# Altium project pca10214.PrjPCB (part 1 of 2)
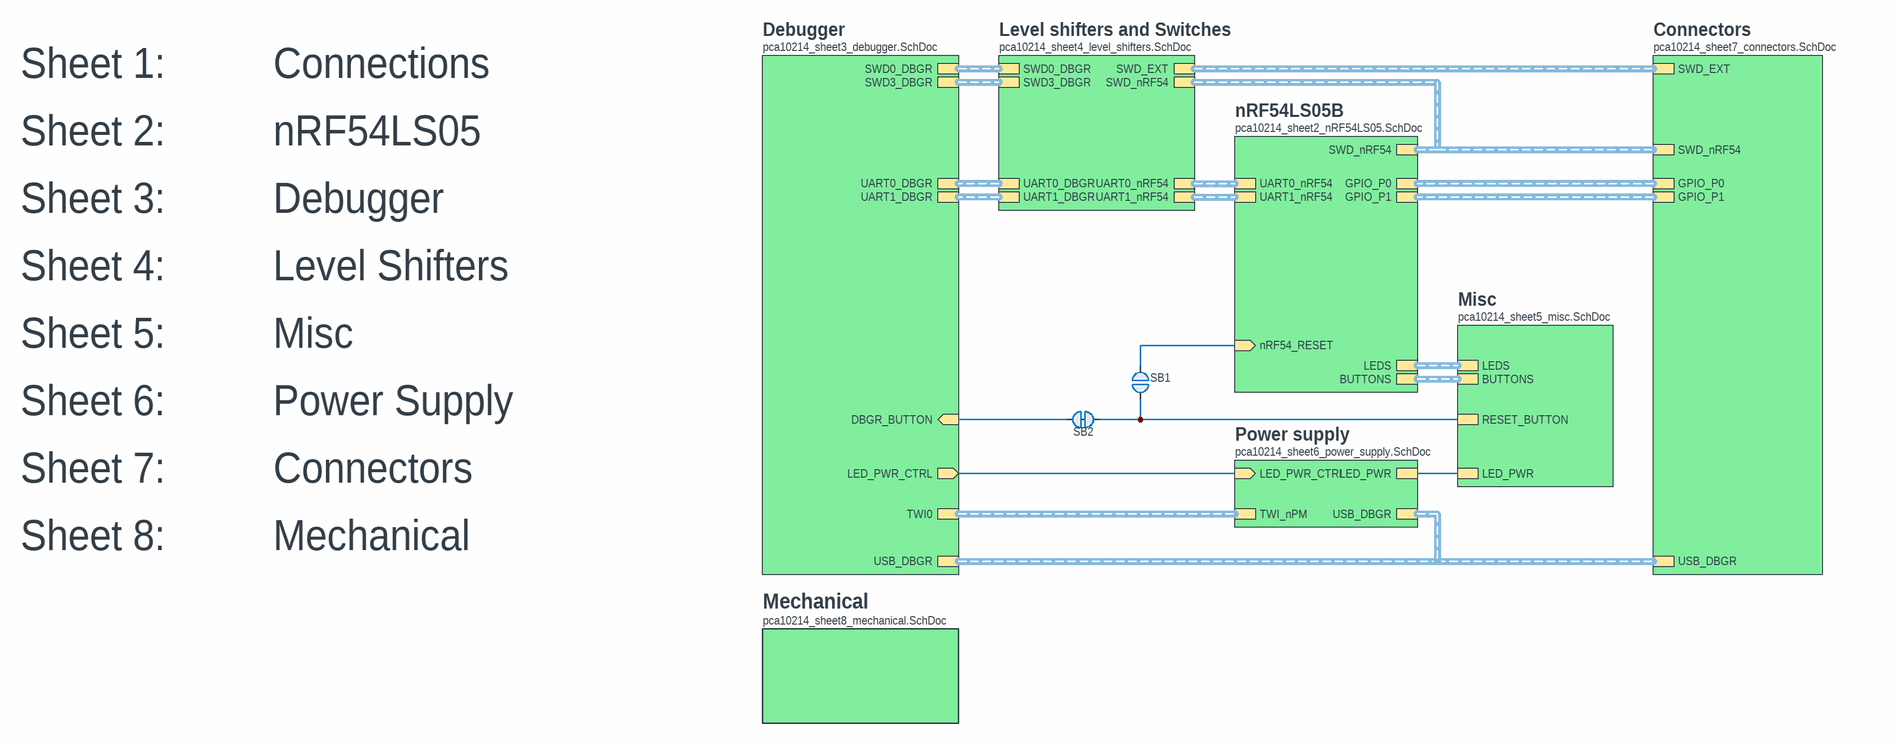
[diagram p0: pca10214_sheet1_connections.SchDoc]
SurfaceFinish: ENIG Gold; SoldermaskColor: Blue; SilkscreenColor: White; ProjectNumber: 4561; ProductName: nRF54LS05-DK; PCBStackup: 4001; PCBRevision: 0116KJP; PCBNumber: 401006; PCARevision: 0.3.1; PCAName: PCA10214; Organization: Nordic Semiconductor; NrOfLayers: 4; Dielectric: FR-4; Designer: KJP; Compliance: RoHS, REACH, Halogen-Free; Classification: PUBLIC; BoardTitle: nRF54LS05 DK; BoardThickness: 1.6mm
8 sheets, 205 parts. Net scope: hierarchical (ports join the sheet entries above them; power ports are global).
Board files: 401006.PcbDoc, 401006 _panel.PcbDoc
Sheets:
  pca10214_sheet1_connections.SchDoc
    nRF54LS05B = pca10214_sheet2_nRF54LS05.SchDoc
    Debugger = pca10214_sheet3_debugger.SchDoc
    Level shifters and Switches = pca10214_sheet4_level_shifters.SchDoc
    Misc = pca10214_sheet5_misc.SchDoc
    Power supply = pca10214_sheet6_power_supply.SchDoc
    Connectors = pca10214_sheet7_connectors.SchDoc
    Mechanical = pca10214_sheet8_mechanical.SchDoc

## Sheet pca10214_sheet1_connections.SchDoc: =BoardTitle+' - Connections'
size A3; Organization: Nordic Semiconductor; DocumentNumber: 1; Revision: 0.3.1; SheetNumber: 1; SheetTotal: 8; Author: KJP; CompanyName: Nordic Semiconductor; DrawnBy: KJP; DocumentSize: A4

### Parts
SB1  Solderbridge  [Solderbridge]  (value not drawn)  (no BOM)
SB2  Solderbridge  [Solderbridge_Shorted]  (value not drawn)  (net tie, no BOM)

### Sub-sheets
Connectors = pca10214_sheet7_connectors.SchDoc: SWD_nRF54 (harness SWD), SWD_EXT (harness SWD), GPIO_P0 (harness GPIO_P0), GPIO_P1 (harness GPIO_P1), USB_DBGR (harness USB)
Debugger = pca10214_sheet3_debugger.SchDoc: DBGR_BUTTON (in), SWD0_DBGR (harness SWD), UART0_DBGR (harness UART_DBGR), USB_DBGR (harness USB), UART1_DBGR (harness UART_DBGR), TWI0 (harness TWI), SWD3_DBGR (harness SWD), LED_PWR_CTRL (out)
Level shifters and Switches = pca10214_sheet4_level_shifters.SchDoc: SWD0_DBGR (harness SWD), SWD_EXT (harness SWD), UART0_nRF54 (harness UART), UART1_nRF54 (harness UART), SWD3_DBGR (harness SWD), SWD_nRF54 (harness SWD), UART0_DBGR (harness UART_DBGR), UART1_DBGR (harness UART_DBGR)
Mechanical = pca10214_sheet8_mechanical.SchDoc: no entries
Misc = pca10214_sheet5_misc.SchDoc: BUTTONS (harness UI), LEDS (harness UI), RESET_BUTTON, LED_PWR
nRF54LS05B = pca10214_sheet2_nRF54LS05.SchDoc: BUTTONS (harness UI), LEDS (harness UI), GPIO_P0 (harness GPIO_P0), UART0_nRF54 (harness UART), GPIO_P1 (harness GPIO_P1), UART1_nRF54 (harness UART), SWD_nRF54 (harness SWD), nRF54_RESET (in)
Power supply = pca10214_sheet6_power_supply.SchDoc: TWI_nPM (harness TWI), LED_PWR_CTRL (in), LED_PWR, USB_DBGR (harness USB)

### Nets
DBGR_BUTTON: SB2.2 ; sheet Debugger/DBGR_BUTTON
LED_PWR_CTRL: sheet Debugger/LED_PWR_CTRL, sheet Power supply/LED_PWR_CTRL
NRESET: SB1.1 ; sheet nRF54LS05B/nRF54_RESET
NetC64_2: sheet Misc/LED_PWR, sheet Power supply/LED_PWR
NetSB1_2: SB1.2 SB2.1 ; sheet Misc/RESET_BUTTON

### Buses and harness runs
harness sheet Connectors/GPIO_P0 = sheet nRF54LS05B/GPIO_P0
harness sheet Connectors/GPIO_P1 = sheet nRF54LS05B/GPIO_P1
harness sheet Connectors/SWD_EXT = sheet Level shifters and Switches/SWD_EXT
harness sheet Connectors/SWD_nRF54 = sheet Level shifters and Switches/SWD_nRF54 = sheet nRF54LS05B/SWD_nRF54
harness sheet Connectors/USB_DBGR = sheet Debugger/USB_DBGR = sheet Power supply/USB_DBGR
harness sheet Debugger/SWD0_DBGR = sheet Level shifters and Switches/SWD0_DBGR
harness sheet Debugger/SWD3_DBGR = sheet Level shifters and Switches/SWD3_DBGR
harness sheet Debugger/TWI0 = sheet Power supply/TWI_nPM
harness sheet Debugger/UART0_DBGR = sheet Level shifters and Switches/UART0_DBGR
harness sheet Debugger/UART1_DBGR = sheet Level shifters and Switches/UART1_DBGR
harness sheet Level shifters and Switches/UART0_nRF54 = sheet nRF54LS05B/UART0_nRF54
harness sheet Level shifters and Switches/UART1_nRF54 = sheet nRF54LS05B/UART1_nRF54
harness sheet Misc/BUTTONS = sheet nRF54LS05B/BUTTONS
harness sheet Misc/LEDS = sheet nRF54LS05B/LEDS

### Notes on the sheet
- Sheet 1:          Connections
- Sheet 2:          nRF54LS05
- Sheet 4:          Level Shifters
- Sheet 3:          Debugger
- Sheet 5:          Misc
- Sheet 6:          Power Supply
- Sheet 7:          Connectors
- Sheet 8:          Mechanical

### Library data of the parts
SB1 = Solderbridge: Manufacturer: N.A.; Part number NEMS: 100500458; Pad Count: 2; Component Status: Active; System: Connector
SB2 = Solderbridge Shorted: Shorted Solderbridge; Manufacturer: N.A.; Part number NEMS: 100500459; Pad Count: 2; Component Status: Active; System: Connector

## Sheet pca10214_sheet2_nRF54LS05.SchDoc: =BoardTitle+' - nRF54LS05B'
size A3; Organization: Nordic Semiconductor; DocumentNumber: 2; Revision: 0.3.1; SheetNumber: 2; SheetTotal: 8; Author: KJP; CompanyName: Nordic Semiconductor; DrawnBy: KJP; DocumentSize: A4
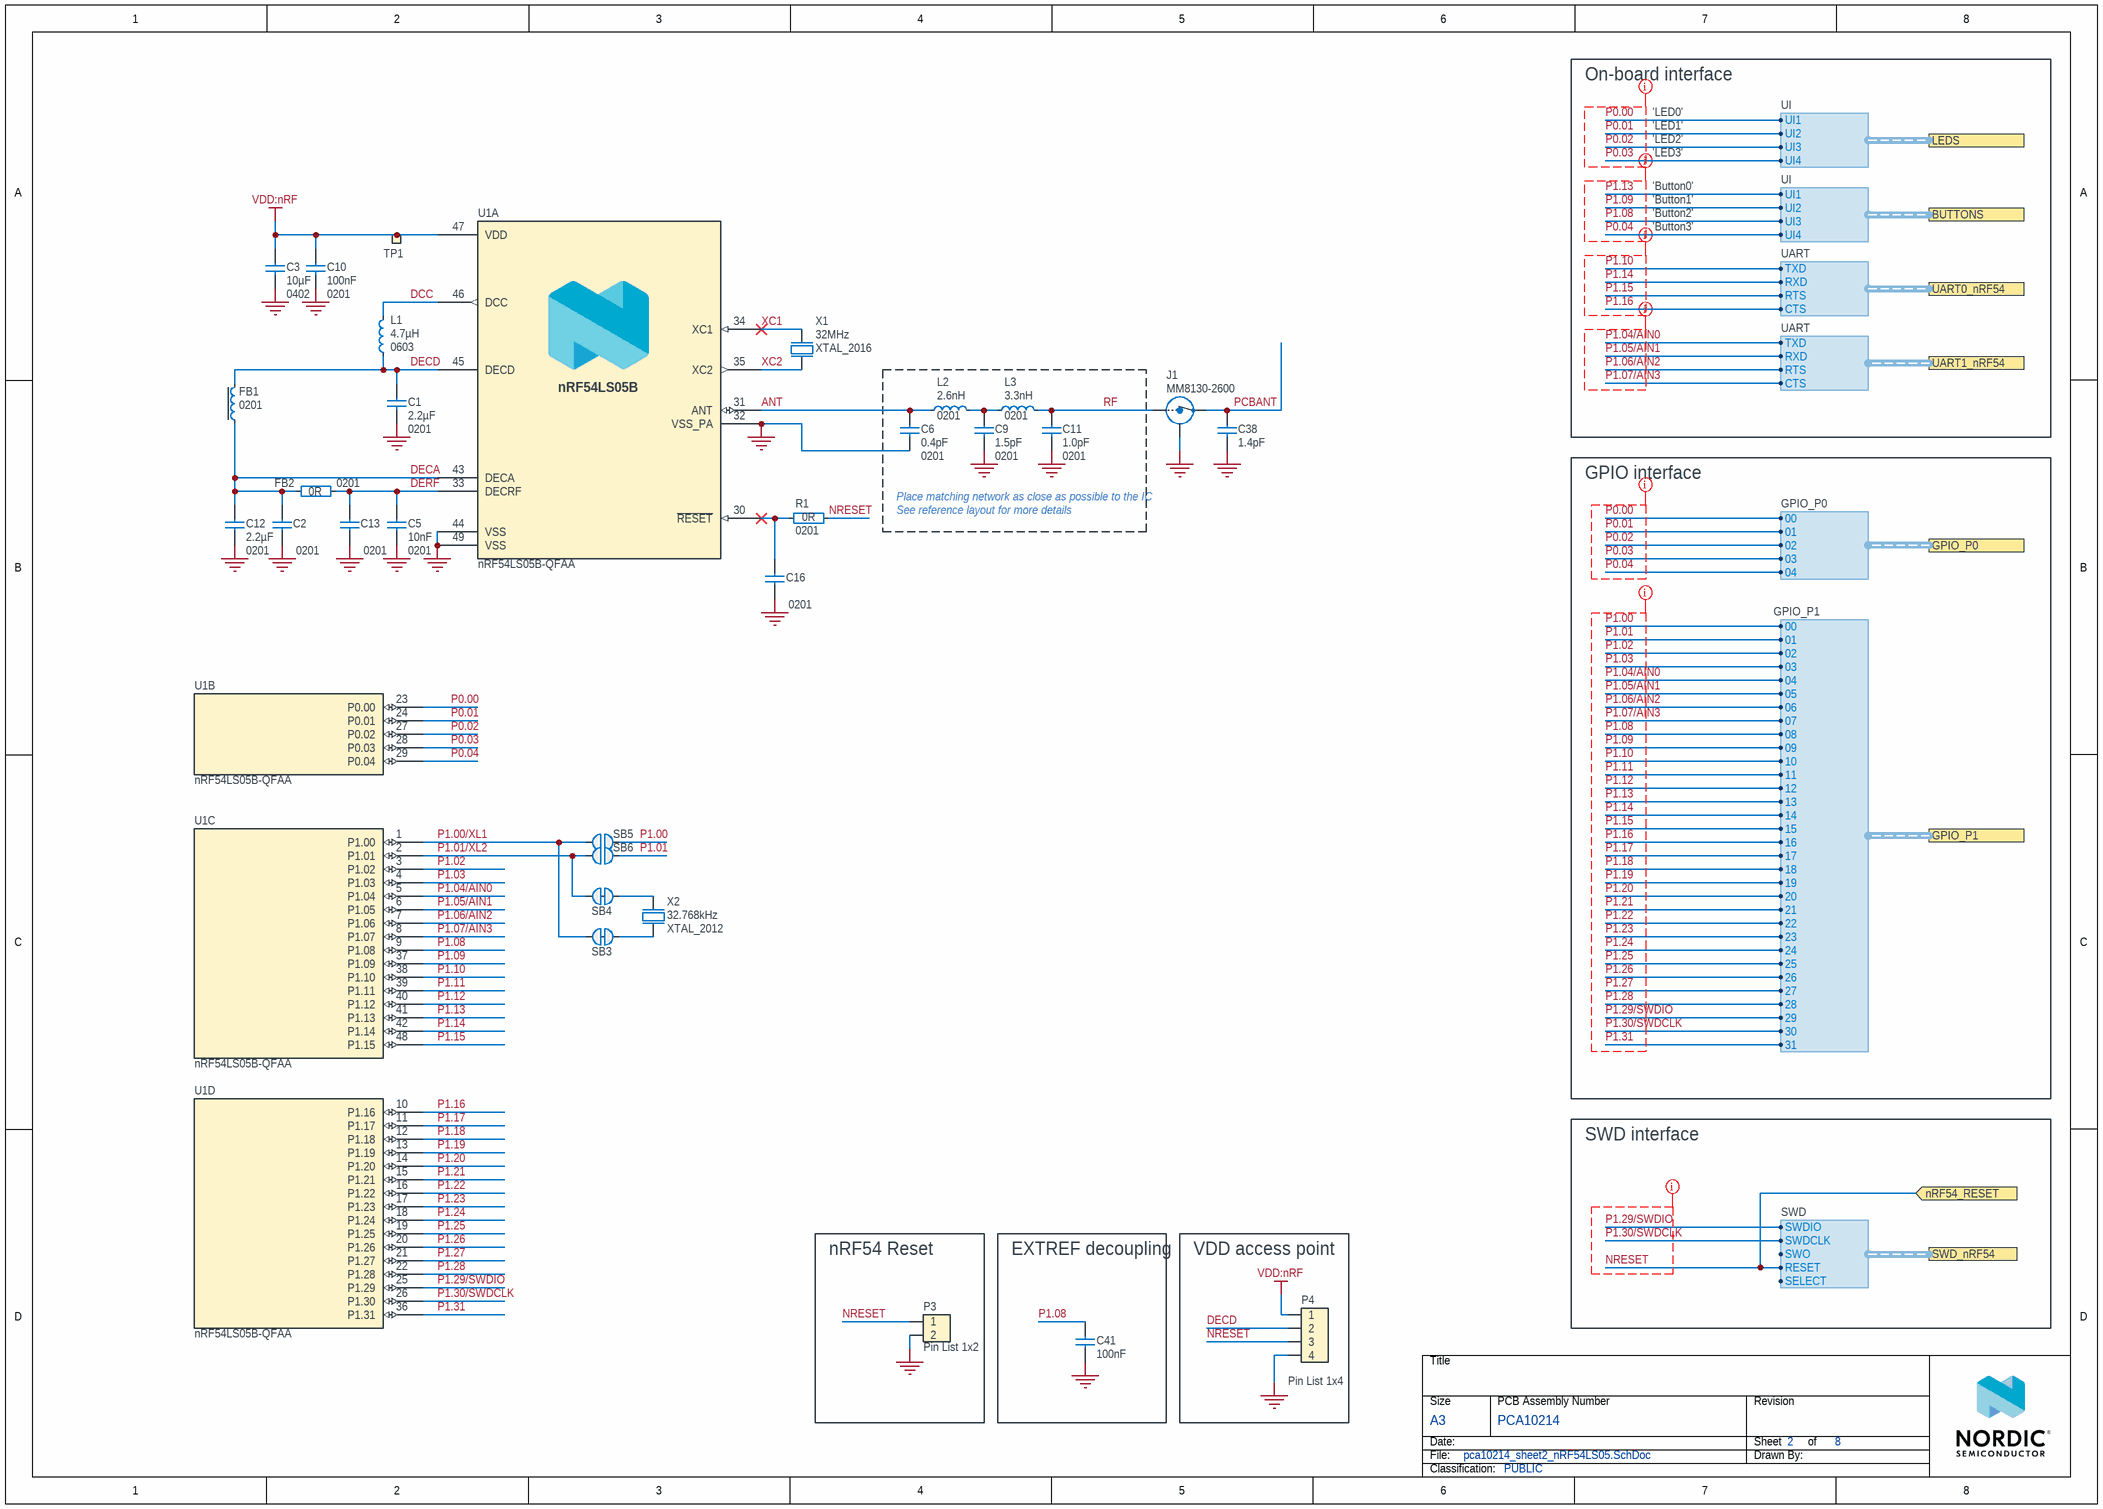
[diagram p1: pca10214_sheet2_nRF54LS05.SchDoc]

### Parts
C1  2.2µF  Footprint Doc: 0201  [CAPC0603X03L_C]
C2  Footprint Doc: 0201  [CAPC0603X03L_C_NC]  (hidden comment: N.C.)
C3  10µF  Footprint Doc: 0402  [CAPC1005X04L]
C5  Footprint Doc: 0201  [CAPC0603X03L_C]  (hidden comment: 10nF)
C6  0.4pF  Footprint Doc: 0201  [CAPC0603X03L_C]
C9  1.5pF  Footprint Doc: 0201  [CAPC0603X03L_C]
C10  100nF  Footprint Doc: 0201  [CAPC0603X03L_C]
C11  1.0pF  Footprint Doc: 0201  [CAPC0603X03L_C]
C12  2.2µF  Footprint Doc: 0201  [CAPC0603X03L_C]
C13  Footprint Doc: 0201  [CAPC0603X03L_C_NC]  (hidden comment: N.C.)
C16  Footprint Doc: 0201  [CAPC0603X03L_C_NC]  (hidden comment: N.C.)
C38  1.4pF  [CAPC0603X03L_C]
C41  100nF  [CAPC1005X04L]
FB1  Footprint Doc: 0201  [INDC0603X03L_C]  (hidden comment: 120R/0.2A)
FB2  Footprint Doc: 0201  [RESC0603X03L_C]  (hidden comment: 0R)
J1  MM8130-2600  [COAXIAL-SWF]
L1  4.7µH  Footprint Doc: 0603  [INDC1608X06L]
L2  2.6nH  Footprint Doc: 0201  [INDC0603X03L_C]
L3  3.3nH  Footprint Doc: 0201  [INDC0603X03L_C]
P3  Pin List 1x2  [LIST_1x2]
P4  Pin List 1x4  [LIST_1x4]
R1  0R  Footprint Doc: 0201  [RESC0603X03L_C]
SB3  Solderbridge  [Solderbridge_SHORTED_0.4]  (value not drawn)  (net tie, no BOM)
SB4  Solderbridge  [Solderbridge_SHORTED_0.4]  (value not drawn)  (net tie, no BOM)
SB5  Solderbridge  [Solderbridge_0.4]  (value not drawn)  (no BOM)
SB6  Solderbridge  [Solderbridge_0.4]  (value not drawn)  (no BOM)
TP1  Ø1.5mm,SMD  [TP_SMD_D1.5mm]  (value not drawn)  (no BOM)
U1  nRF54LS05B-QFAA  [QFN49P40_600x600x90L40x20T460N]  (parts A,B,C,D of 4)
X1  32MHz  Footprint Doc: XTAL_2016  [BT-XTAL_2016]
X2  32.768kHz  [XTAL_2012]

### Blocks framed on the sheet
nRF54 Reset: P3
EXTREF decoupling: C41
VDD access point: P4

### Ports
BUTTONS (harness UI), GPIO_P0 (harness GPIO_P0), GPIO_P1 (harness GPIO_P1), LEDS (harness UI), nRF54_RESET (in), SWD_nRF54 (harness SWD), UART0_nRF54 (harness UART), UART1_nRF54 (harness UART)

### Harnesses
SWD: SWDIO, SWDCLK, SWO, RESET, SELECT
UART: RTS, CTS, RXD, TXD
GPIO_P0: 02, 03, 04, 00, 01
UI: UI2, UI1, UI3, UI4
GPIO_P1: 02, 03, 04, 00, 01, 05, 06, 07, 08, 09, 10, 11, 12, 13, 14, 15, 16, 17, 18, 19, 20, 21, 22, 23, 24, 25, 26, 27, 28, 29, 30, 31

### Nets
GND: C1.1 C2.1 C3.1 C5.1 C6.1 C9.1 C10.2 C11.1 C12.1 C13.1 C16.1 C38.1 C41.1 J1.2(Shield) P3.2 P4.4 U1.32(VSS_PA) U1.44(VSS) U1.49(VSS) X1.2(GND) X1.4(GND)
VDD:nRF: C3.2 C10.1 P4.1 TP1.1 U1.47(VDD)
ANT: C6.2 L2.1 U1.31(ANT)
DCC: L1.1 U1.46(DCC)
DECA: C2.2 C12.2 FB1.2 FB2.2 U1.43(DECA)
DECD: C1.2 FB1.1 L1.2 P4.2 U1.45(DECD)
DERF: C5.2 C13.2 FB2.1 U1.33(DECRF)
NRESET: P3.1 P4.3 R1.2 ; port nRF54_RESET, port SWD_nRF54.RESET
P0.00: U1.23(P0.00) ; port GPIO_P0.00, port LEDS.UI1
P0.01: U1.24(P0.01) ; port GPIO_P0.01, port LEDS.UI2
P0.02: U1.27(P0.02) ; port GPIO_P0.02, port LEDS.UI3
P0.03: U1.28(P0.03) ; port GPIO_P0.03, port LEDS.UI4
P0.04: U1.29(P0.04) ; port GPIO_P0.04, port BUTTONS.UI4
P1.00: SB5.2 ; port GPIO_P1.00
P1.00/XL1: SB3.1 SB5.1 U1.1(P1.00)
P1.01: SB6.2 ; port GPIO_P1.01
P1.01/XL2: SB4.1 SB6.1 U1.2(P1.01)
P1.02: U1.3(P1.02) ; port GPIO_P1.02
P1.03: U1.4(P1.03) ; port GPIO_P1.03
P1.04/AIN0: U1.5(P1.04) ; port UART1_nRF54.TXD, port GPIO_P1.04
P1.05/AIN1: U1.6(P1.05) ; port UART1_nRF54.RXD, port GPIO_P1.05
P1.06/AIN2: U1.7(P1.06) ; port UART1_nRF54.RTS, port GPIO_P1.06
P1.07/AIN3: U1.8(P1.07) ; port UART1_nRF54.CTS, port GPIO_P1.07
P1.08: C41.2 U1.9(P1.08) ; port BUTTONS.UI3, port GPIO_P1.08
P1.09: U1.37(P1.09) ; port BUTTONS.UI2, port GPIO_P1.09
P1.10: U1.38(P1.10) ; port UART0_nRF54.TXD, port GPIO_P1.10
P1.11: U1.39(P1.11) ; port GPIO_P1.11
P1.12: U1.40(P1.12) ; port GPIO_P1.12
P1.13: U1.41(P1.13) ; port BUTTONS.UI1, port GPIO_P1.13
P1.14: U1.42(P1.14) ; port UART0_nRF54.RXD, port GPIO_P1.14
P1.15: U1.48(P1.15) ; port UART0_nRF54.RTS, port GPIO_P1.15
P1.16: U1.10(P1.16) ; port UART0_nRF54.CTS, port GPIO_P1.16
P1.17: U1.11(P1.17) ; port GPIO_P1.17
P1.18: U1.12(P1.18) ; port GPIO_P1.18
P1.19: U1.13(P1.19) ; port GPIO_P1.19
P1.20: U1.14(P1.20) ; port GPIO_P1.20
P1.21: U1.15(P1.21) ; port GPIO_P1.21
P1.22: U1.16(P1.22) ; port GPIO_P1.22
P1.23: U1.17(P1.23) ; port GPIO_P1.23
P1.24: U1.18(P1.24) ; port GPIO_P1.24
P1.25: U1.19(P1.25) ; port GPIO_P1.25
P1.26: U1.20(P1.26) ; port GPIO_P1.26
P1.27: U1.21(P1.27) ; port GPIO_P1.27
P1.28: U1.22(P1.28) ; port GPIO_P1.28
P1.29/SWDIO: U1.25(P1.29) ; port SWD_nRF54.SWDIO, port GPIO_P1.29
P1.30/SWDCLK: U1.26(P1.30) ; port SWD_nRF54.SWDCLK, port GPIO_P1.30
P1.31: U1.36(P1.31) ; port GPIO_P1.31
PCBANT: C38.2 J1.3(OUT)
RF: C11.2 J1.1(IN) L3.2
XC1: U1.34(XC1) X1.1(inp)
XC2: U1.35(XC2) X1.3(out)
NetC9_2: C9.2 L2.2 L3.1
NetC16_2: C16.2 R1.1 U1.30(~{RESET})
NetSB3_2: SB3.2 X2.1(inp)
NetSB4_2: SB4.2 X2.2(out)

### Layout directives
net class UART0: P1.10, P1.14, P1.15, P1.16
net class UART1: P1.04/AIN0, P1.05/AIN1, P1.06/AIN2, P1.07/AIN3
net class LEDS: P0.00, P0.01, P0.02, P0.03
net class BUTTONS: P0.04, P1.08, P1.09, P1.13
net class GPIO_P0: P0.00, P0.01, P0.02, P0.03, P0.04
net class GPIO_P1: P1.00, P1.01, P1.02, P1.03, P1.04/AIN0, P1.05/AIN1, P1.06/AIN2, P1.07/AIN3, P1.08, P1.09, P1.10, P1.11, P1.12, P1.13, P1.14, P1.15, P1.16, P1.17, P1.18, P1.19, P1.20, P1.21, P1.22, P1.23, P1.24, P1.25, P1.26, P1.27, P1.28, P1.29/SWDIO, P1.30/SWDCLK, P1.31
net class SWD_nRF54: NRESET, P1.29/SWDIO, P1.30/SWDCLK

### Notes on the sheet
- On-board interface
- 'LED1'
- 'LED2'
- 'LED3'
- 'LED0'
- 'Button1'
- 'Button2'
- 'Button3'
- 'Button0'
- See reference layout for more details
- Place matching network as close as possible to the IC
- GPIO interface
- SWD interface

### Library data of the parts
C1 = C0201-2µ2-2.5V-X6T-GRM033D80E225ME47D: Capacitor, Ceramic, 2.2µF 2.5V X6T 0201,±20%; Manufacturer: Murata; Manufacturer Part Number: GRM033R61A225KE47; Part number NEMS: 100200527; Component Status: Active; Pad Count: 2; Note: 2.5V, 20%, X6T; Artikkelnr Noca: N.A.
C2 C13 C16 = C0201-N.C.: Not mounted; Manufacturer: N.A.; Part number NEMS: 100200001; Component Status: Active; Pad Count: 2; Note: Chip Cap; Assembly: Not mounted
C3 = C0402-10µF-6.3V-X6S: Capacitor, X6S, ±20%, 6.3V; Manufacturer: N.A.; Part number NEMS: 100200478; Component Status: Active; Pad Count: 2
C5 = C0201-10n-6.3V-X7R: Capacitor, X7R, 6.3V; Manufacturer: Murata; Manufacturer Part Number: GRM033R70J103KA01D; Part number NEMS: 100200407; Component Status: Active; Pad Count: 2; Artikkelnr Noca: N.A.
C6 = C0201-0p4-25V-C0G-GJM0335C1ER40WB01D: Capacitor, C0G, ±0.05pF, 25V; Manufacturer: Murata; Part number NEMS: 100200706; Component Status: Active; Pad Count: 2; Artikkelnr Noca: N.A.
C9 = C0201-1.5p-25V-NP0-GJM0335C1E1R5WB01: Capacitor, NP0, ±0.05pF, 25V, High Q; Manufacturer: Murata; Part number NEMS: 100200477; Component Status: Active; Pad Count: 2; Artikkelnr Noca: N.A.
C10 = C0201-100n-10V-X7R: Capacitor, X7R, ±10%; Manufacturer: N.A.; Part number NEMS: 100200469; Note: 10V; Pad Count: 2; Component Status: Active
C11 = C0201-1p0-25V-COG-GJM0335C1E1R0WB01: CAP CER 1.0PF 25V C0G/NP0 0201; Manufacturer: Murata; Part number NEMS: 100200676; Component Status: Active; Pad Count: 2; Artikkelnr Noca: N.A.
C12 = C0201-2µ2: Capacitor, X5R, ±20%; Manufacturer: N.A.; Part number NEMS: 100200375; Component Status: Active; Pad Count: 2; Note: 10V
C38 = C0201-1.4p-25V-GJM0335C1E1R4WB01D: Capacitor, C0G, ±0.05pF, 25V; Manufacturer: Murata; Part number NEMS: 100200553; Pad Count: 2; Artikkelnr Noca: N.A.; Component Status: Active
C41 = C0402-100n: Capacitor, X7R, ±10%; Manufacturer: N.A.; Part number IPS: 00000005296; Part number NEMS: 100200184; Component Status: Active; Pad Count: 2; Note: 16V; Artikkelnr Noca: 20039200
FB1 = FB0201-120R@100M-200mA-BLM03AG121SN1D: Ferrite Bead, 120 Ohm @ 100MHz, 200mA, 500 mOhm Max; Manufacturer: Murata; Part number NEMS: 100300419; Component Status: Active; Pad Count: 2; Artikkelnr Noca: N.A.
FB2 R1 = R0201-0R-5%-0.05W-RC0201JR-070RL: 0 Ohms Jumper 0.05W, 1/20W Chip Resistor 0201 (0603 Metric) Moisture Resistant Thick Film; Manufacturer: Yageo; Part number NEMS: 100100652; Component Status: Active; Pad Count: 2; Note: Chip Res 5%; Artikkelnr Noca: N.A.
J1 = MM8130-2600: Coaxial Connector with Switch; Manufacturer: Murata; Part number IPS: 00000009955; Part number Norautron: 26030338; Part number NEMS: 100500400; Component Status: Active; Pad Count: 3; Note: N.A.; Artikkelnr Noca: 55029011
L1 = L0603-4µ7-MLZ1608M4R7WT000: Inductor, 120mA, ±20%, 0.65R; Manufacturer: TDK Corporation; Part number NEMS: 100300440; Component Status: Active; Pad Count: 2; Note: Power Inductor ±20%; Artikkelnr Noca: N.A.
L2 = L0201-2n6-HQ-Murata: Inductor, 600mA, ±0.1ｎH, 120mOhm; Manufacturer: Murata; Part number NEMS: 100300213; Component Status: Active; Pad Count: 2; Note: -55°C ~ 125°C; Artikkelnr Noca: N.A.
L3 = L0201-3n3-HQ-Murata: Inductor, 500mA, ±0.1ｎH, 170mOhm; Manufacturer: Murata; Part number NEMS: 100300220; Component Status: Active; Pad Count: 2; Note: -55°C ~ 125°C; Artikkelnr Noca: N.A.
P3 = Pin List 1x2: Pin List 1x2, 2.54mm (100mil); Manufacturer: N.A.; Part number NEMS: 100500297; Component Status: Active; Pad Count: 2; Artikkelnr Noca: 56019040; System: Connector
P4 = Pin List 1x4: Pin List 1x4, 2.54mm (100mil); Manufacturer: N.A.; Part number NEMS: 100500309; Component Status: Active; Pad Count: 4; Artikkelnr Noca: 56019092; System: Connector
SB3 SB4 = Solderbridge Shorted 0.4mm: Shorted Solderbridge; Manufacturer: N.A.; Part number NEMS: 100500561; Component Status: Active; Pad Count: 2; System: Connector
SB5 SB6 = Solderbridge 0.4mm: Manufacturer: N.A.; Part number NEMS: 100500560; Component Status: Active; Pad Count: 2; System: Connector
TP1 = TP_SMD_Ø1.5MM: 1.5mm circular SMD testpad; Manufacturer: Nordic Semiconductor; Manufacturer Part Number: N.A.; Part number NEMS: 100500477; Pad Count: 1; Component Status: Active
U1 = nRF54LS05B-QFAA: Ultra-low-power Bluetooth LE SoC with 508 KB NVM and 96 KB RAM, supporting Bluetooth LE and 2.4 GHz proprietary protocols; Manufacturer: Nordic Semiconductor; Part number NEMS: 102000422; Component Status: Active; Pad Count: 49; Note: N.A.
X1 = XTAL_SMD2016_32MHz_8pF_Kyocera: XTAL SMD 2016, 32MHz, Cl=8pF, Tot: ±40ppm; Manufacturer Part Number: CX2016DB32000D0WZRC1; Part number IPS: 00000007827; Part number Norautron: 26511136; Part number NEMS: 101600039; Component Status: Active; Pad Count: 4; Note: XTAL SMD 32.000MHz; Artikkelnr Noca: 22010022
X2 = XTAL_SMD2012_32.768kHz_9pF_TXC: XTAL SMD 2012, 32.768kHz, 9pF, ±20ppm; Manufacturer: TXC Corporation; Manufacturer Part Number: 9HT11-32.768KDZC-T; Part number NEMS: 101600107; Component Status: Active; Pad Count: 2; Note: XTAL SMD 32.768kHz; Artikkelnr Noca: N.A.

## Sheet pca10214_sheet3_debugger.SchDoc: =BoardTitle+' - Debugger'
size A3; Organization: Nordic Semiconductor; DocumentNumber: 3; Revision: 0.3.1; SheetNumber: 3; SheetTotal: 8; Author: KJP; CompanyName: Nordic Semiconductor; DrawnBy: KJP; DocumentSize: A4
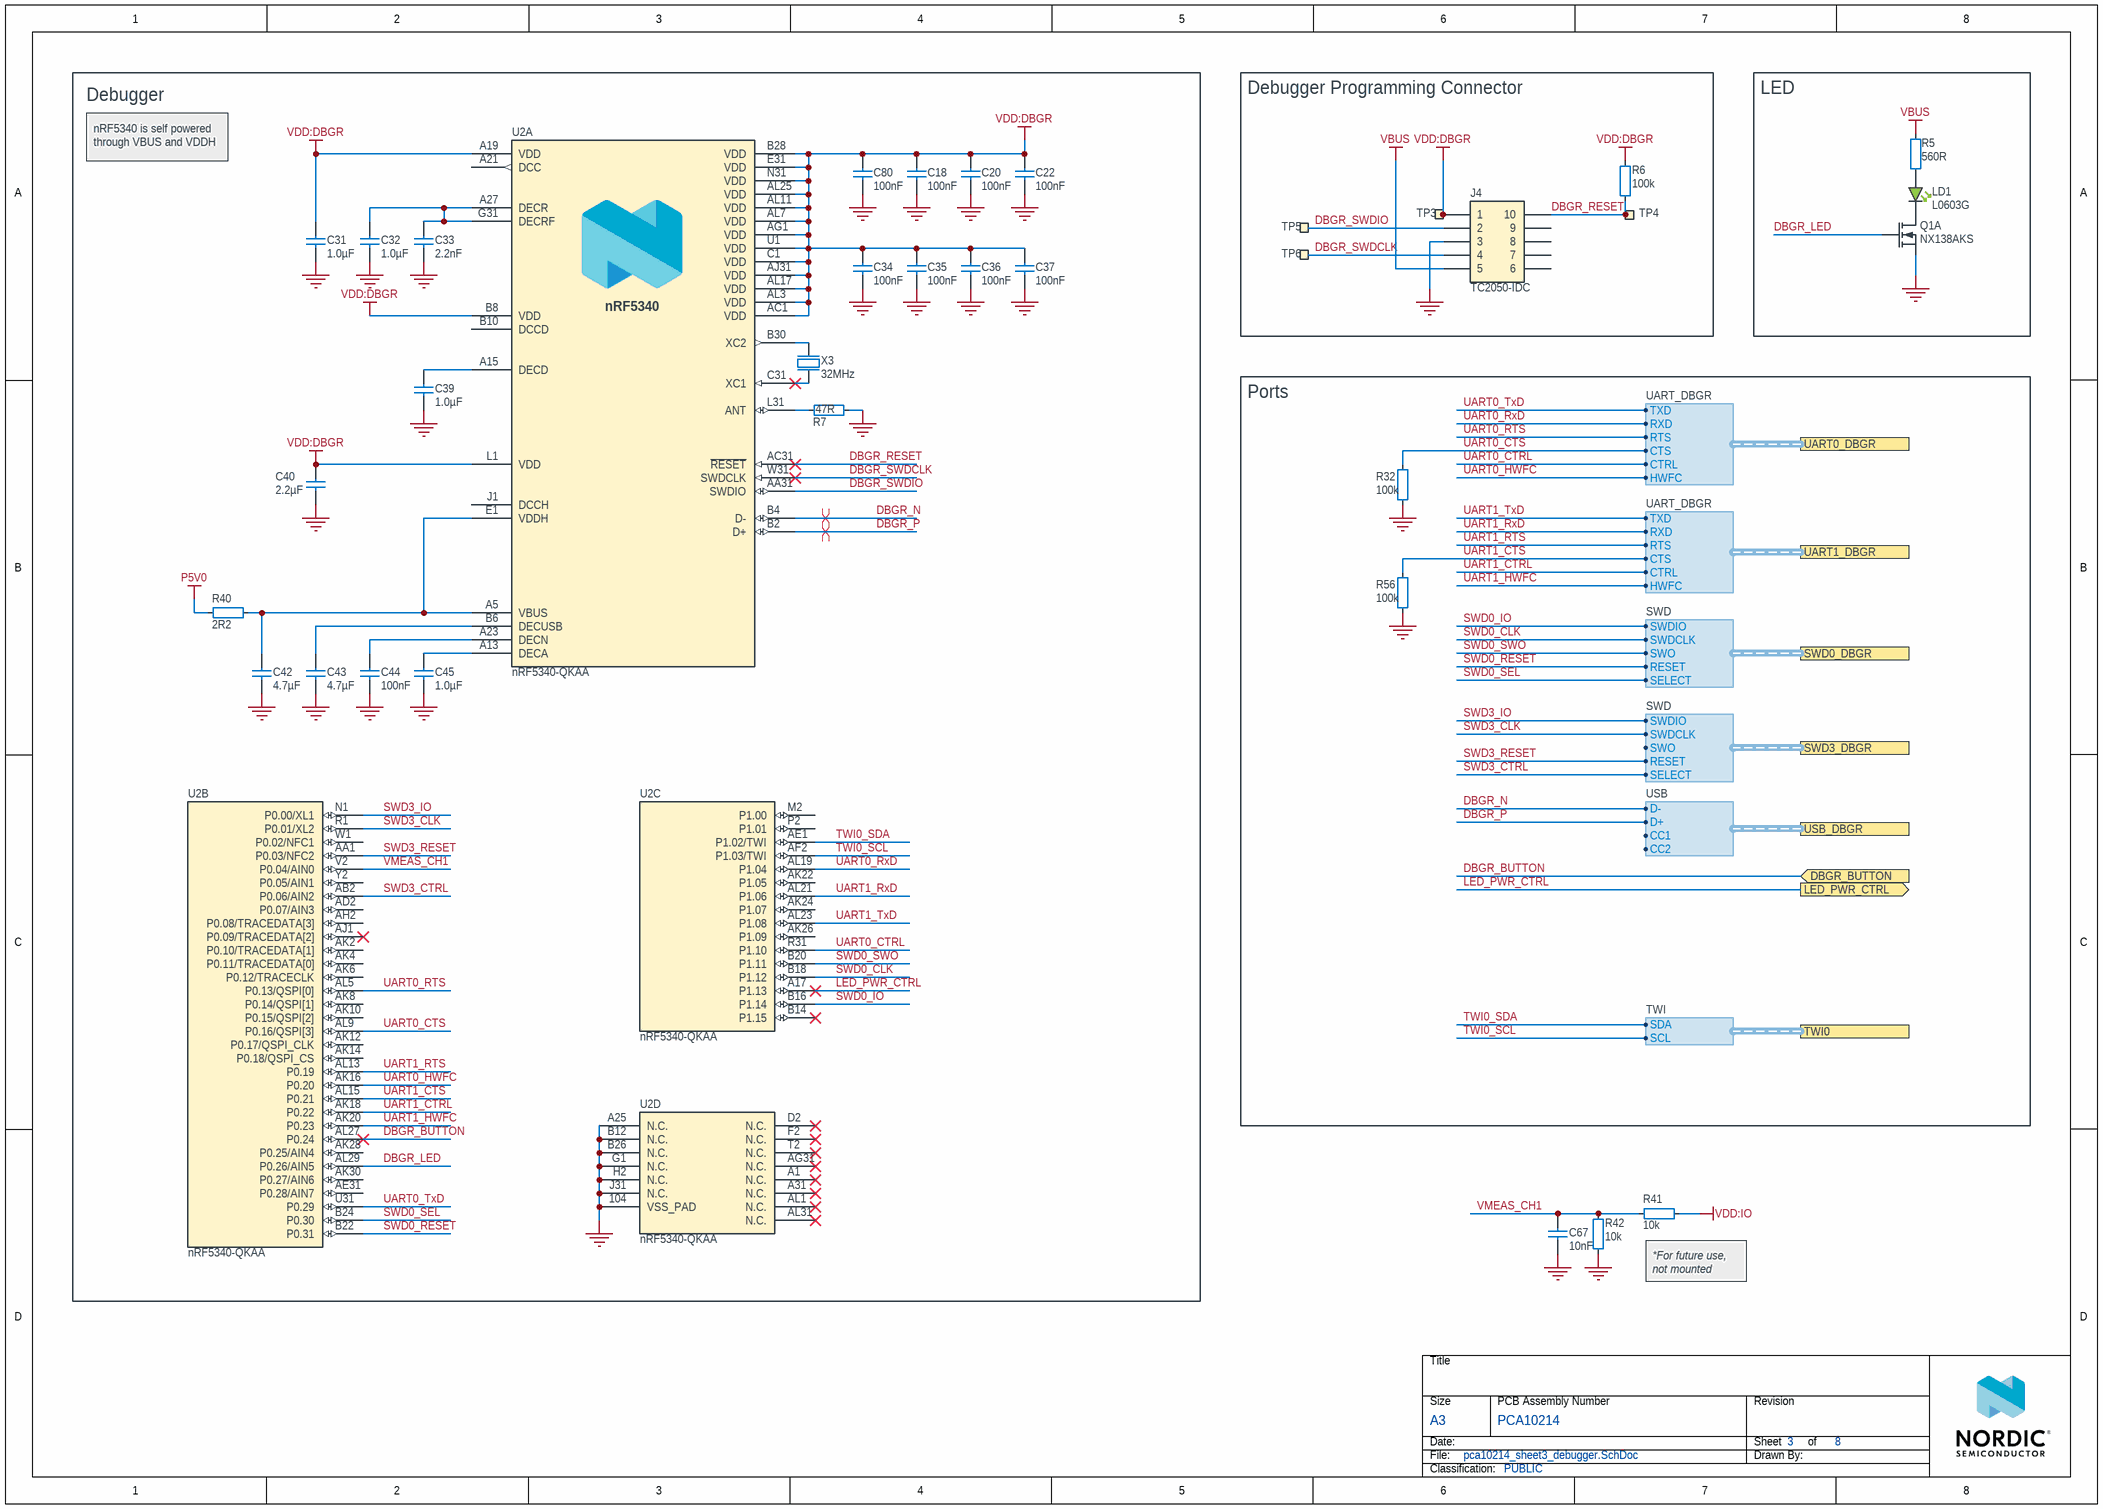
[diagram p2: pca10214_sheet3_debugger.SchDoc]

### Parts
C18  100nF  [CAPC0603X03L_C]
C20  100nF  [CAPC0603X03L_C]
C22  100nF  [CAPC0603X03L_C]
C31  1.0µF  [CAPC1005X04L]
C32  1.0µF  [CAPC1005X04L]
C33  2.2nF  [CAPC0603X03L_C]
C34  100nF  [CAPC0603X03L_C]
C35  100nF  [CAPC0603X03L_C]
C36  100nF  [CAPC0603X03L_C]
C37  100nF  [CAPC0603X03L_C]
C39  1.0µF  [CAPC1005X04L]
C40  2.2µF  [CAPC1608X06L]
C42  4.7µF  [CAPC1608X06L]
C43  4.7µF  [CAPC1608X06L]
C44  100nF  [CAPC0603X03L_C]
C45  1.0µF  [CAPC1005X04L]
C67  10nF  [CAPC0603X03L_C]
C80  100nF  [CAPC0603X03L_C]
J4  TC2050-IDC  [TC2050-IDC-NLFP]  (no BOM)
LD1  L0603G  [LED_0603_G]
Q1  NX138AKS  [TSSOP6]  (part A of 2)
R5  560R  [RESC0603X03L_C]
R6  100k  [RESC0603X03L_C]
R7  47R  [RESC0603X03L_C]
R32  100k  [RESC0603X03L_C]
R40  2R2  [RESC0603X03L_C]
R41  10k  [RESC0603X03L_C]
R42  10k  [RESC0603X03L_C]
R56  100k  [RESC0603X03L_C]
TP3  Ø1.5mm,SMD  [TP_SMD_D1.5mm]  (value not drawn)  (no BOM)
TP4  Ø1.5mm,SMD  [TP_SMD_D1.5mm]  (value not drawn)  (no BOM)
TP5  Ø1.5mm,SMD  [TP_SMD_D1.5mm]  (value not drawn)  (no BOM)
TP6  Ø1.5mm,SMD  [TP_SMD_D1.5mm]  (value not drawn)  (no BOM)
U2  nRF5340-QKAA  [AQFN40P700X700X85_HS-99N]  (parts A,B,C,D of 4)
X3  32MHz  [BT-XTAL_2016]

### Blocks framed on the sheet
Debugger: C18 C20 C22 C31-C37 C39 C40 C42-C45 C80 R7 R40 U2 X3
Debugger Programming Connector: J4 R6 TP3-TP6
LED: LD1 Q1 R5
Ports: R32 R56

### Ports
DBGR_BUTTON (in), LED_PWR_CTRL (out), SWD0_DBGR (harness SWD), SWD3_DBGR (harness SWD), TWI0 (harness TWI), UART0_DBGR (harness UART_DBGR), UART1_DBGR (harness UART_DBGR), USB_DBGR (harness USB)

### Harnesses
SWD: SWDIO, SWDCLK, SWO, RESET, SELECT
UART_DBGR: RTS, CTS, RXD, TXD, HWFC, CTRL
TWI: SCL, SDA
USB: D+, D-, CC1, CC2

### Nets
GND: C18.2 C20.2 C22.2 C31.2 C32.1 C33.2 C34.2 C35.2 C36.2 C37.2 C39.1 C40.2 C42.2 C43.2 C44.2 C45.1 C67.2 C80.2 J4.3 Q1.1(S1) R7.2 R32.2 R42.1 R56.2 U2.104(VSS_PAD) U2.A25(N.C.) U2.B12(N.C.) U2.B26(N.C.) U2.G1(N.C.) U2.H2(N.C.) U2.J31(N.C.) X3.2(GND) X3.4(GND)
P5V0: R40.2
VBUS: J4.5 R5.2
VDD:DBGR: C18.1 C20.1 C22.1 C31.1 C34.1 C35.1 C36.1 C37.1 C40.1 C80.1 J4.1 R6.2 TP3.1 U2.A19(VDD) U2.AC1(VDD) U2.AG1(VDD) U2.AJ31(VDD) U2.AL3(VDD) U2.AL7(VDD) U2.AL11(VDD) U2.AL17(VDD) U2.AL25(VDD) U2.B8(VDD) U2.B28(VDD) U2.C1(VDD) U2.E31(VDD) U2.L1(VDD) U2.N31(VDD) U2.U1(VDD)
VDD:IO: R41.2
DBGR_BUTTON: U2.AL27(P0.24) ; port DBGR_BUTTON
DBGR_LED: Q1.2(G1) U2.AL29(P0.26/AIN5)
DBGR_N: U2.B4(D-) ; port USB_DBGR.D-
DBGR_P: U2.B2(D+) ; port USB_DBGR.D+
DBGR_RESET: J4.10 R6.1 TP4.1 U2.AC31(~{RESET})
DBGR_SWDCLK: J4.4 TP6.1 U2.W31(SWDCLK)
DBGR_SWDIO: J4.2 TP5.1 U2.AA31(SWDIO)
LED_PWR_CTRL: U2.A17(P1.13) ; port LED_PWR_CTRL
SWD0_CLK: U2.B18(P1.12) ; port SWD0_DBGR.SWDCLK
SWD0_IO: U2.B16(P1.14) ; port SWD0_DBGR.SWDIO
SWD0_RESET: U2.B22(P0.31) ; port SWD0_DBGR.RESET
SWD0_SEL: U2.B24(P0.30) ; port SWD0_DBGR.SELECT
SWD0_SWO: U2.B20(P1.11) ; port SWD0_DBGR.SWO
SWD3_CLK: U2.R1(P0.01/XL2) ; port SWD3_DBGR.SWDCLK
SWD3_CTRL: U2.AB2(P0.06/AIN2) ; port SWD3_DBGR.SELECT
SWD3_IO: U2.N1(P0.00/XL1) ; port SWD3_DBGR.SWDIO
SWD3_RESET: U2.AA1(P0.03/NFC2) ; port SWD3_DBGR.RESET
TWI0_SCL: U2.AF2(P1.03/TWI) ; port TWI0.SCL
TWI0_SDA: U2.AE1(P1.02/TWI) ; port TWI0.SDA
UART0_CTRL: U2.R31(P1.10) ; port UART0_DBGR.CTRL
UART0_CTS: R32.1 U2.AL9(P0.16/QSPI[3]) ; port UART0_DBGR.CTS
UART0_HWFC: U2.AK16(P0.20) ; port UART0_DBGR.HWFC
UART0_RTS: U2.AL5(P0.13/QSPI[0]) ; port UART0_DBGR.RTS
UART0_RxD: U2.AL19(P1.04) ; port UART0_DBGR.RXD
UART0_TxD: U2.U31(P0.29) ; port UART0_DBGR.TXD
UART1_CTRL: U2.AK18(P0.22) ; port UART1_DBGR.CTRL
UART1_CTS: R56.1 U2.AL15(P0.21) ; port UART1_DBGR.CTS
UART1_HWFC: U2.AK20(P0.23) ; port UART1_DBGR.HWFC
UART1_RTS: U2.AL13(P0.19) ; port UART1_DBGR.RTS
UART1_RxD: U2.AL21(P1.06) ; port UART1_DBGR.RXD
UART1_TxD: U2.AL23(P1.08) ; port UART1_DBGR.TXD
VMEAS_CH1: C67.1 R41.1 R42.2 U2.V2(P0.04/AIN0)
NetC32_2: C32.2 C33.1 U2.A27(DECR) U2.G31(DECRF)
NetC39_2: C39.2 U2.A15(DECD)
NetC42_1: C42.1 R40.1 U2.A5(VBUS) U2.E1(VDDH)
NetC43_1: C43.1 U2.B6(DECUSB)
NetC44_1: C44.1 U2.A23(DECN)
NetC45_2: C45.2 U2.A13(DECA)
NetLD1_1: LD1.1(C) Q1.6(D1)
NetLD1_2: LD1.2(A) R5.1
NetR7_1: R7.1 U2.L31(ANT)
NetU2_B30: U2.B30(XC2) X3.3(out)
NetU2_C31: U2.C31(XC1) X3.1(inp)

Not connected (* = marked no-connect by the designer): J4 6 7 8 9; U2 A1(N.C.)* A21(DCC) A31(N.C.)* AD2(P0.07/AIN3) AE31(P0.28/AIN7) AG31(N.C.)* AH2(P0.08/TRACEDATA[3]) AJ1(P0.09/TRACEDATA[2])* AK2(P0.10/TRACEDATA[1]) AK4(P0.11/TRACEDATA[0]) AK6(P0.12/TRACECLK) AK8(P0.14/QSPI[1]) AK10(P0.15/QSPI[2]) AK12(P0.17/QSPI_CLK) AK14(P0.18/QSPI_CS) AK22(P1.05) AK24(P1.07) AK26(P1.09) AK28(P0.25/AIN4) AK30(P0.27/AIN6) AL1(N.C.)* AL31(N.C.)* B10(DCCD) B14(P1.15)* D2(N.C.)* F2(N.C.)* J1(DCCH) M2(P1.00) P2(P1.01) T2(N.C.)* W1(P0.02/NFC1) Y2(P0.05/AIN1)

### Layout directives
differential pair; differential pair class DBGR; net class DBGR_USB: DBGR_N, DBGR_P

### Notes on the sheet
- nRF5340 is self powered through VBUS and VDDH
- (near R41) *For future use, not mounted

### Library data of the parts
C18 C20 C22 C34-C37 C44 C80 = C0201-100n: Capacitor, X5R, ±10%; Manufacturer: N.A.; Part number IPS: 00000001248, 00000002505; Part number Norautron: 262071862; Part number NEMS: 100200078; Pad Count: 2; Note: 16V; Component Status: Active
C31 C32 C39 C45 = C0402-1µ0-6.3V-X5R-10%: Capacitor, X5R, ±10%, 6.3V; Manufacturer: N.A.; Part number Norautron: 26207137; Part number NEMS: 100200498; Pad Count: 2; Component Status: Active
C33 = C0201-2n2: Capacitor, X7R, ±10%, 10V; Manufacturer: N.A.; Part number IPS: 00000001778; Part number Norautron: 26470002; Part number NEMS: 100200060; Pad Count: 2; Component Status: Active
C40 = C0603-2µ2-6.3V-X7R: Capacitor, X7R, ±10%, 6.3V; Manufacturer: N.A.; Part number NEMS: 100200272; Artikkelnr Noca: 20039322; Pad Count: 2; Component Status: Active
C42 C43 = C0603-4µ7-10V-X7S: Capacitor, X7S, ±10%, 10V; Manufacturer: N.A.; Part number IPS: 00000001779; Part number NEMS: 100200351; Pad Count: 2; Artikkelnr Noca: 20030013; Component Status: Active
C67 = C0201-10n: Capacitor, X7R, ±10%; Manufacturer: N.A.; Part number IPS: 00000003480; Part number Norautron: 26621779; Part number NEMS: 100200067; Note: 10V; Assembly: Not Mounted; Pad Count: 2; Component Status: Active
J4 = TC2050-IDC-NLFP: CBL PLUG-OF-NAILS 10-PIN; Manufacturer: Tag-Connect LLC; Part number NEMS: 100500463; Artikkelnr Noca: N.A.; Pad Count: 10; Component Status: Active; System: Connector
LD1 = VS 25C7M5: LED, Green, 0603, 573nm, Vf=2.0V, 24mcd, - 40 to +85°C; Manufacturer: Victory Electronics; Part number IPS: 00000001274, 00000009961; Part number Norautron: 26313411; Part number NEMS: 101400097; Pad Count: 2; Note: N.A.; Artikkelnr Noca: 13019193; Component Status: Active
Q1 = NX138AKS: MOSFET 2N-CH 60V 0.17A TSSOP6 (SOT363); Manufacturer: Nexperia; Manufacturer Part Number: NX138AKSX; Part number NEMS: 101300207; Component Status: Active; Pad Count: 6; Note: N.A.
R5 = R0201-560: Resistor, ±1%, 0.05W; Manufacturer: N.A.; Part number NEMS: 100100038; Note: Chip Res 1%; Pad Count: 2; Component Status: Active
R6 R32 R56 = R0201-100k: Resistor, ±1%, 0.05W; Manufacturer: N.A.; Part number IPS: 00000001419; Part number Norautron: 26108487; Part number NEMS: 100100080; Note: Chip Res 1%; Pad Count: 2; Component Status: Active
R7 = R0201-47R: Resistor, ±1%, 0.05W; Manufacturer: N.A.; Part number IPS: 00000004794; Part number Norautron: 26108300; Part number NEMS: 100100022; Component Status: Active; Pad Count: 2; Note: Chip Res 1%
R40 = R0201-2R2: Resistor, ±1%, 0.05W; Manufacturer: N.A.; Part number Norautron: 26470029; Part number NEMS: 100100006; Pad Count: 2; Note: Chip Res 1%; Component Status: Active
R41 R42 = R0201-10k: Resistor, ±1%, 0.05W; Manufacturer: N.A.; Part number IPS: 00000001255; Part number Norautron: 26107101; Part number NEMS: 100100065; Component Status: Active; Pad Count: 2; Note: Chip Res 1%
TP3-TP6 = TP_SMD_Ø1.5MM: as TP1 on sheet pca10214_sheet2_nRF54LS05
U2 = nRF5340-QKAA: Multi-protocol Bluetooth Low Energy, IEEE 802.15.4, ANT and 2.4GHz proprietary system-on-chip; Manufacturer: Nordic Semiconductor; Part number NEMS: 102000153; Component Status: Active; Pad Count: 98; Note: N.A.
X3 = XTAL_SMD2016_32MHz_8pF_Golledge: XTAL SMD 2016, 32MHz, Cl=8pF, Tol: ±10ppm, Stab: ±15ppm; Manufacturer Part Number: MP06003; Part number IPS: 00000001431; Part number Norautron: N.A.; Part number NEMS: 101600041; Component Status: Active; Pad Count: 4; Note: XTAL SMD 32.000MHz; Artikkelnr Noca: 22010050

## Sheet pca10214_sheet4_level_shifters.SchDoc: =BoardTitle+' - Level Shifters'
size A3; Organization: Nordic Semiconductor; DocumentNumber: 4; Revision: 0.3.1; SheetNumber: 4; SheetTotal: 8; Author: KJP; CompanyName: Nordic Semiconductor; DrawnBy: KJP; DocumentSize: A4
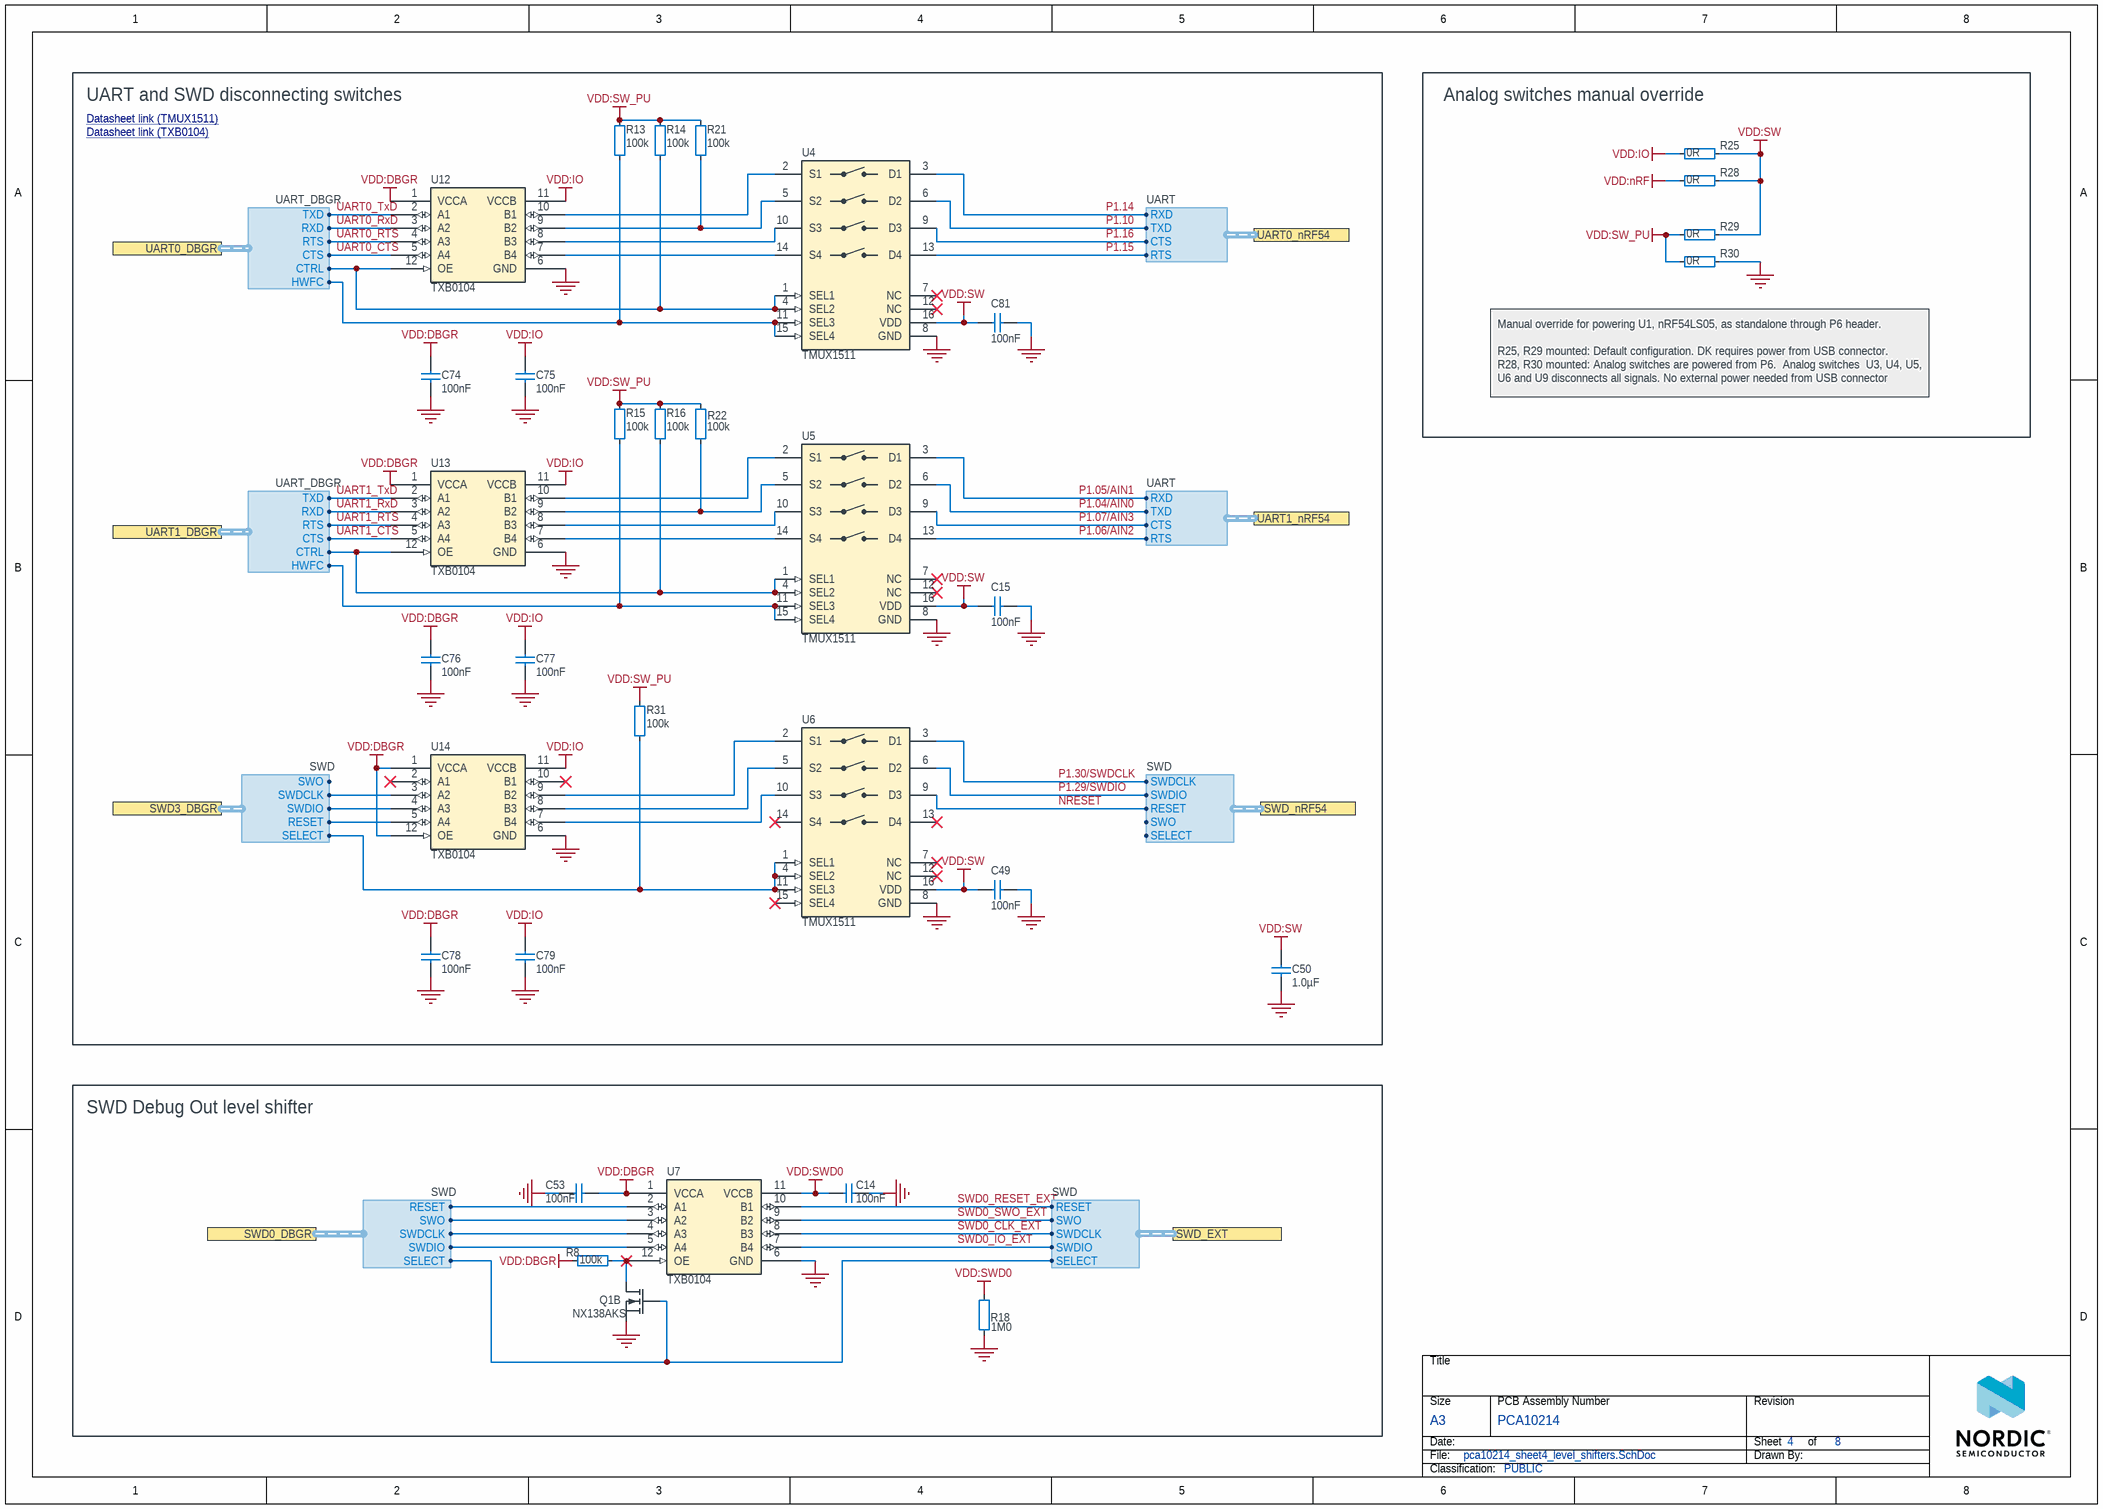
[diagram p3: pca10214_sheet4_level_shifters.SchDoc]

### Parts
C14  100nF  [CAPC0603X03L_C]
C15  100nF  [CAPC0603X03L_C]
C49  100nF  [CAPC0603X03L_C]
C50  1.0µF  [CAPC1005X04L]
C53  100nF  [CAPC0603X03L_C]
C74  100nF  [CAPC0603X03L_C]
C75  100nF  [CAPC0603X03L_C]
C76  100nF  [CAPC0603X03L_C]
C77  100nF  [CAPC0603X03L_C]
C78  100nF  [CAPC0603X03L_C]
C79  100nF  [CAPC0603X03L_C]
C81  100nF  [CAPC0603X03L_C]
Q1  NX138AKS  [TSSOP6]  (part B of 2)
R8  100k  [RESC0603X03L_C]
R13  100k  [RESC0603X03L_C]
R14  100k  [RESC0603X03L_C]
R15  100k  [RESC0603X03L_C]
R16  100k  [RESC0603X03L_C]
R18  1M0  [RESC0603X03L_C]
R21  100k  [RESC0603X03L_C]
R22  100k  [RESC0603X03L_C]
R25  0R  [RESC1005X04L]
R28  0R  [RESC1005X04L]
R29  0R  [RESC1005X04L]
R30  0R  [RESC1005X04L]
R31  100k  [RESC0603X03L_C]
U4  TMUX1511  [XQFN40P180X260X50-16N]
U5  TMUX1511  [XQFN40P180X260X50-16N]
U6  TMUX1511  [XQFN40P180X260X50-16N]
U7  TXB0104  [QFN12P40_170X200X55L50X20]
U12  TXB0104  [QFN12P40_170X200X55L50X20]
U13  TXB0104  [QFN12P40_170X200X55L50X20]
U14  TXB0104  [QFN12P40_170X200X55L50X20]

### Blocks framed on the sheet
UART and SWD disconnecting switches: C15 C49 C50 C74-C79 C81 R13-R16 R21 R22 R31 U4-U6 U12-U14
Analog switches manual override: R25 R28-R30
SWD Debug Out level shifter: C14 C53 Q1 R8 R18 U7

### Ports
SWD0_DBGR (harness SWD), SWD3_DBGR (harness SWD), SWD_EXT (harness SWD), SWD_nRF54 (harness SWD), UART0_DBGR (harness UART_DBGR), UART0_nRF54 (harness UART), UART1_DBGR (harness UART_DBGR), UART1_nRF54 (harness UART)

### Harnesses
SWD: SWDIO, SWDCLK, SWO, RESET, SELECT
UART: RTS, CTS, RXD, TXD
UART_DBGR: RTS, CTS, RXD, TXD, HWFC, CTRL

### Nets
GND: C14.2 C15.2 C49.2 C50.1 C53.1 C74.2 C75.2 C76.2 C77.2 C78.2 C79.2 C81.2 Q1.4(S2) R18.1 R30.2 U4.8(GND) U5.8(GND) U6.8(GND) U7.6(GND) U12.6(GND) U13.6(GND) U14.6(GND)
VDD:DBGR: C53.2 C74.1 C76.1 C78.1 R8.2 U7.1(VCCA) U12.1(VCCA) U13.1(VCCA) U14.1(VCCA) U14.12(OE)
VDD:IO: C75.1 C77.1 C79.1 R25.1 U12.11(VCCB) U13.11(VCCB) U14.11(VCCB)
VDD:nRF: R28.1
VDD:SW: C15.1 C49.1 C50.2 C81.1 R25.2 R28.2 R29.2 U4.16(VDD) U5.16(VDD) U6.16(VDD)
VDD:SW_PU: R13.1 R14.1 R15.1 R16.1 R21.1 R22.1 R29.1 R30.1 R31.1
VDD:SWD0: C14.1 R18.2 U7.11(VCCB)
NRESET: U6.9(D3) ; port SWD_nRF54.RESET
P1.04/AIN0: U5.6(D2) ; port UART1_nRF54.TXD
P1.05/AIN1: U5.3(D1) ; port UART1_nRF54.RXD
P1.06/AIN2: U5.13(D4) ; port UART1_nRF54.RTS
P1.07/AIN3: U5.9(D3) ; port UART1_nRF54.CTS
P1.10: U4.6(D2) ; port UART0_nRF54.TXD
P1.14: U4.3(D1) ; port UART0_nRF54.RXD
P1.15: U4.13(D4) ; port UART0_nRF54.RTS
P1.16: U4.9(D3) ; port UART0_nRF54.CTS
P1.29/SWDIO: U6.6(D2) ; port SWD_nRF54.SWDIO
P1.30/SWDCLK: U6.3(D1) ; port SWD_nRF54.SWDCLK
SWD0_CLK: U7.4(A3) ; port SWD0_DBGR.SWDCLK
SWD0_CLK_EXT: U7.8(B3) ; port SWD_EXT.SWDCLK
SWD0_IO: U7.5(A4) ; port SWD0_DBGR.SWDIO
SWD0_IO_EXT: U7.7(B4) ; port SWD_EXT.SWDIO
SWD0_RESET: U7.2(A1) ; port SWD0_DBGR.RESET
SWD0_RESET_EXT: U7.10(B1) ; port SWD_EXT.RESET
SWD0_SEL: Q1.5(G2) ; port SWD0_DBGR.SELECT, port SWD_EXT.SELECT
SWD0_SWO: U7.3(A2) ; port SWD0_DBGR.SWO
SWD0_SWO_EXT: U7.9(B2) ; port SWD_EXT.SWO
SWD3_CLK: U14.3(A2) ; port SWD3_DBGR.SWDCLK
SWD3_CTRL: R31.2 U6.1(SEL1) U6.4(SEL2) U6.11(SEL3) ; port SWD3_DBGR.SELECT
SWD3_IO: U14.4(A3) ; port SWD3_DBGR.SWDIO
SWD3_RESET: U14.5(A4) ; port SWD3_DBGR.RESET
UART0_CTRL: R14.2 U4.1(SEL1) U4.4(SEL2) U12.12(OE) ; port UART0_DBGR.CTRL
UART0_CTS: U12.5(A4) ; port UART0_DBGR.CTS
UART0_HWFC: R13.2 U4.11(SEL3) U4.15(SEL4) ; port UART0_DBGR.HWFC
UART0_RTS: U12.4(A3) ; port UART0_DBGR.RTS
UART0_RxD: U12.3(A2) ; port UART0_DBGR.RXD
UART0_TxD: U12.2(A1) ; port UART0_DBGR.TXD
UART1_CTRL: R16.2 U5.1(SEL1) U5.4(SEL2) U13.12(OE) ; port UART1_DBGR.CTRL
UART1_CTS: U13.5(A4) ; port UART1_DBGR.CTS
UART1_HWFC: R15.2 U5.11(SEL3) U5.15(SEL4) ; port UART1_DBGR.HWFC
UART1_RTS: U13.4(A3) ; port UART1_DBGR.RTS
UART1_RxD: U13.3(A2) ; port UART1_DBGR.RXD
UART1_TxD: U13.2(A1) ; port UART1_DBGR.TXD
NetQ1_3: Q1.3(D2) R8.1 U7.12(OE)
NetR21_2: R21.2 U4.5(S2) U12.9(B2)
NetR22_2: R22.2 U5.5(S2) U13.9(B2)
NetU4_2: U4.2(S1) U12.10(B1)
NetU4_10: U4.10(S3) U12.8(B3)
NetU4_14: U4.14(S4) U12.7(B4)
NetU5_2: U5.2(S1) U13.10(B1)
NetU5_10: U5.10(S3) U13.8(B3)
NetU5_14: U5.14(S4) U13.7(B4)
NetU6_2: U6.2(S1) U14.9(B2)
NetU6_5: U6.5(S2) U14.8(B3)
NetU6_10: U6.10(S3) U14.7(B4)

Not connected (* = marked no-connect by the designer): U4 7(NC)* 12(NC)*; U5 7(NC)* 12(NC)*; U6 7(NC)* 12(NC)* 13(D4)* 14(S4)* 15(SEL4)*; U14 2(A1)* 10(B1)*

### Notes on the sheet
- Datasheet link (TMUX1511) <https://www.ti.com/lit/ds/symlink/tmux1511.pdf?ts=1730882090102&ref_url=https%253A%252F%252Fwww.mouser.dk%252F>
- Datasheet link (TXB0104) <https://www.ti.com/lit/ds/symlink/txb0104.pdf?src-supplier=IHS+Markit>
- Manual override for powering U1, nRF54LS05, as standalone through P6 header.
  R25, R29 mounted: Default configuration. DK requires power from USB connector.
  R28, R30 mounted: Analog switches are powered from P6.  Analog switches  U3, U4, U5, U6 and U9 disconnects all signals. No external power needed from USB connector

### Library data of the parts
C14 C15 C49 C53 C74-C79 C81 = C0201-100n: as C18 on sheet pca10214_sheet3_debugger
C50 = C0402-1µ0-6.3V-X5R-10%: as C31 on sheet pca10214_sheet3_debugger
Q1 = NX138AKS: as Q1 on sheet pca10214_sheet3_debugger
R8 R13-R16 R21 R22 R31 = R0201-100k: as R6 on sheet pca10214_sheet3_debugger
R18 = R0201-1M0: Resistor, ±1%, 0.05W; Manufacturer: N.A.; Part number IPS: 00000001418; Part number Norautron: 26107108; Part number NEMS: 100100093; Component Status: Active; Pad Count: 2; Note: Chip Res 1%
R25 R28-R30 = R0402-0R: Resistor, ±5%, 0.063W; Manufacturer: N.A.; Part number IPS: 00000007128; Part number NEMS: 100100109; Component Status: Active; Pad Count: 2; Note: Chip Res 5%; Artikkelnr Noca: 27049000
U4-U6 = TMUX1511: Low-Capacitance, 1:1 (SPST) 4-Channel, analog switch; Manufacturer: Texas Instruments; Manufacturer Part Number: TMUX1511RSVR; Part number NEMS: 101900847; Component Status: Active; Pad Count: 16; Note: N.A.
U7 U12-U14 = TXB0104RUTR: 4-Bit Bidirectional Level-Shifter/Voltage Translator with Automatic Direction Sensing; Manufacturer: Texas Instruments; Part number NEMS: 101900856; Component Status: Active; Pad Count: 12; Note: Translator, Bidirectional; Artikkelnr Noca: N.A.

## Sheet pca10214_sheet5_misc.SchDoc: =BoardTitle+' - Misc'
size A3; Organization: Nordic Semiconductor; DocumentNumber: 5; Revision: 0.3.1; SheetNumber: 5; SheetTotal: 8; Author: KJP; CompanyName: Nordic Semiconductor; DrawnBy: KJP; DocumentSize: A4
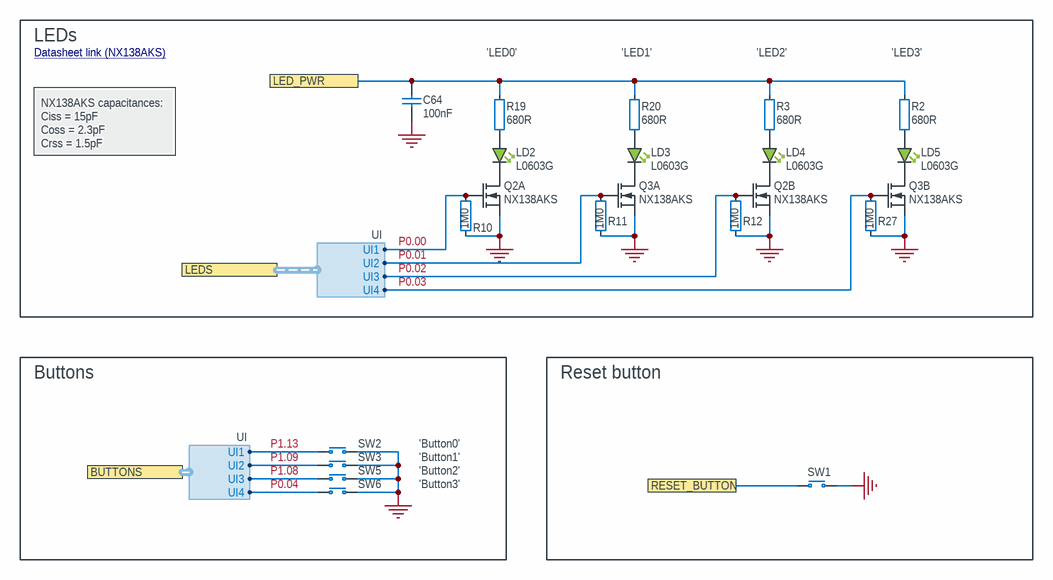
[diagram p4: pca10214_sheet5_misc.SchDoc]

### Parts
C64  100nF  [CAPC0603X03L_C]
LD2  L0603G  [LED_0603_G]
LD3  L0603G  [LED_0603_G]
LD4  L0603G  [LED_0603_G]
LD5  L0603G  [LED_0603_G]
Q2  NX138AKS  [TSSOP6]  (parts A,B of 2)
Q3  NX138AKS  [TSSOP6]  (parts A,B of 2)
R2  680R  [RESC0603X03L_C]
R3  680R  [RESC0603X03L_C]
R10  1M0  [RESC0603X03L_C]
R11  1M0  [RESC0603X03L_C]
R12  1M0  [RESC0603X03L_C]
R19  680R  [RESC0603X03L_C]
R20  680R  [RESC0603X03L_C]
R27  1M0  [RESC0603X03L_C]
SW1  PB SW  [Switch-PB-6.2x6.3mm-SMD]  (value not drawn)
SW2  PB SW  [Switch-PB-6.2x6.3mm-SMD]  (value not drawn)
SW3  PB SW  [Switch-PB-6.2x6.3mm-SMD]  (value not drawn)
SW5  PB SW  [Switch-PB-6.2x6.3mm-SMD]  (value not drawn)
SW6  PB SW  [Switch-PB-6.2x6.3mm-SMD]  (value not drawn)

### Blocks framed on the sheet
LEDs: C64 LD2-LD5 Q2 Q3 R2 R3 R10-R12 R19 R20 R27
Buttons: SW2 SW3 SW5 SW6
Reset button: SW1

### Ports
BUTTONS (harness UI), LED_PWR, LEDS (harness UI), RESET_BUTTON

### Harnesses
UI: UI2, UI1, UI3, UI4
UI: UI2, UI3, UI4, UI1

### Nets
GND: C64.1 Q2.1(S1) Q2.4(S2) Q3.1(S1) Q3.4(S2) R10.2 R11.2 R12.2 R27.2 SW1.1(N.O) SW2.1(N.O) SW3.1(N.O) SW5.1(N.O) SW6.1(N.O)
P0.00: Q2.2(G1) R10.1 ; port LEDS.UI1
P0.01: Q3.2(G1) R11.1 ; port LEDS.UI2
P0.02: Q2.5(G2) R12.1 ; port LEDS.UI3
P0.03: Q3.5(G2) R27.1 ; port LEDS.UI4
P0.04: SW6.2(COM) ; port BUTTONS.UI4
P1.08: SW5.2(COM) ; port BUTTONS.UI3
P1.09: SW3.2(COM) ; port BUTTONS.UI2
P1.13: SW2.2(COM) ; port BUTTONS.UI1
NetC64_2: C64.2 R2.2 R3.2 R19.2 R20.2 ; port LED_PWR
NetLD2_1: LD2.1(C) Q2.6(D1)
NetLD2_2: LD2.2(A) R19.1
NetLD3_1: LD3.1(C) Q3.6(D1)
NetLD3_2: LD3.2(A) R20.1
NetLD4_1: LD4.1(C) Q2.3(D2)
NetLD4_2: LD4.2(A) R3.1
NetLD5_1: LD5.1(C) Q3.3(D2)
NetLD5_2: LD5.2(A) R2.1
NetSB1_2: SW1.2(COM) ; port RESET_BUTTON

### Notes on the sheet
- Datasheet link (NX138AKS) <https://assets.nexperia.com/documents/data-sheet/NX138AKS.pdf>
- (near R19) 'LED0'
- (near R20) 'LED1'
- (near R3) 'LED2'
- (near R2) 'LED3'
- NX138AKS capacitances:
  Ciss = 15pF
  Coss = 2.3pF
  Crss = 1.5pF
- 'Button1'
- 'Button2'
- 'Button3'
- 'Button0'

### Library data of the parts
C64 = C0201-100n: Capacitor, X5R, ±10%; Manufacturer: N.A.; Part number IPS: 00000001248, 00000002505; Part number Norautron: 262071862; Part number NEMS: 100200078; Note: 16V; Pad Count: 2; Component Status: Active
LD2-LD5 = VS 25C7M5: as LD1 on sheet pca10214_sheet3_debugger
Q2 Q3 = NX138AKS: as Q1 on sheet pca10214_sheet3_debugger
R2 R3 R19 R20 = R0201-680: Resistor, ±1%, 0.05W; Manufacturer: N.A.; Part number NEMS: 100100040; Component Status: Active; Pad Count: 2; Note: Chip Res 1%
R10-R12 R27 = R0201-1M0: as R18 on sheet pca10214_sheet4_level_shifters
SW1-SW3 SW5 SW6 = Switch-PB-6.2x6.3mm-SMD: Tactile Switch, SPNO, SMD, 160gf, 6.2x6.3x2.5mm; Manufacturer: Dailywell; Manufacturer Part Number: TS604VM1-025BR-R; Part number IPS: 00000007812; Part number NEMS: 101500001, 101500133; Note: N.A.; Artikkelnr Noca: 50019106; Pad Count: 4; Component Status: Active

## Sheet pca10214_sheet6_power_supply.SchDoc: =BoardTitle+' - Power Supply'
size A3; Organization: Nordic Semiconductor; DocumentNumber: 6; Revision: 0.3.1; SheetNumber: 6; SheetTotal: 8; Author: KJP; CompanyName: Nordic Semiconductor; DrawnBy: KJP; DocumentSize: A4
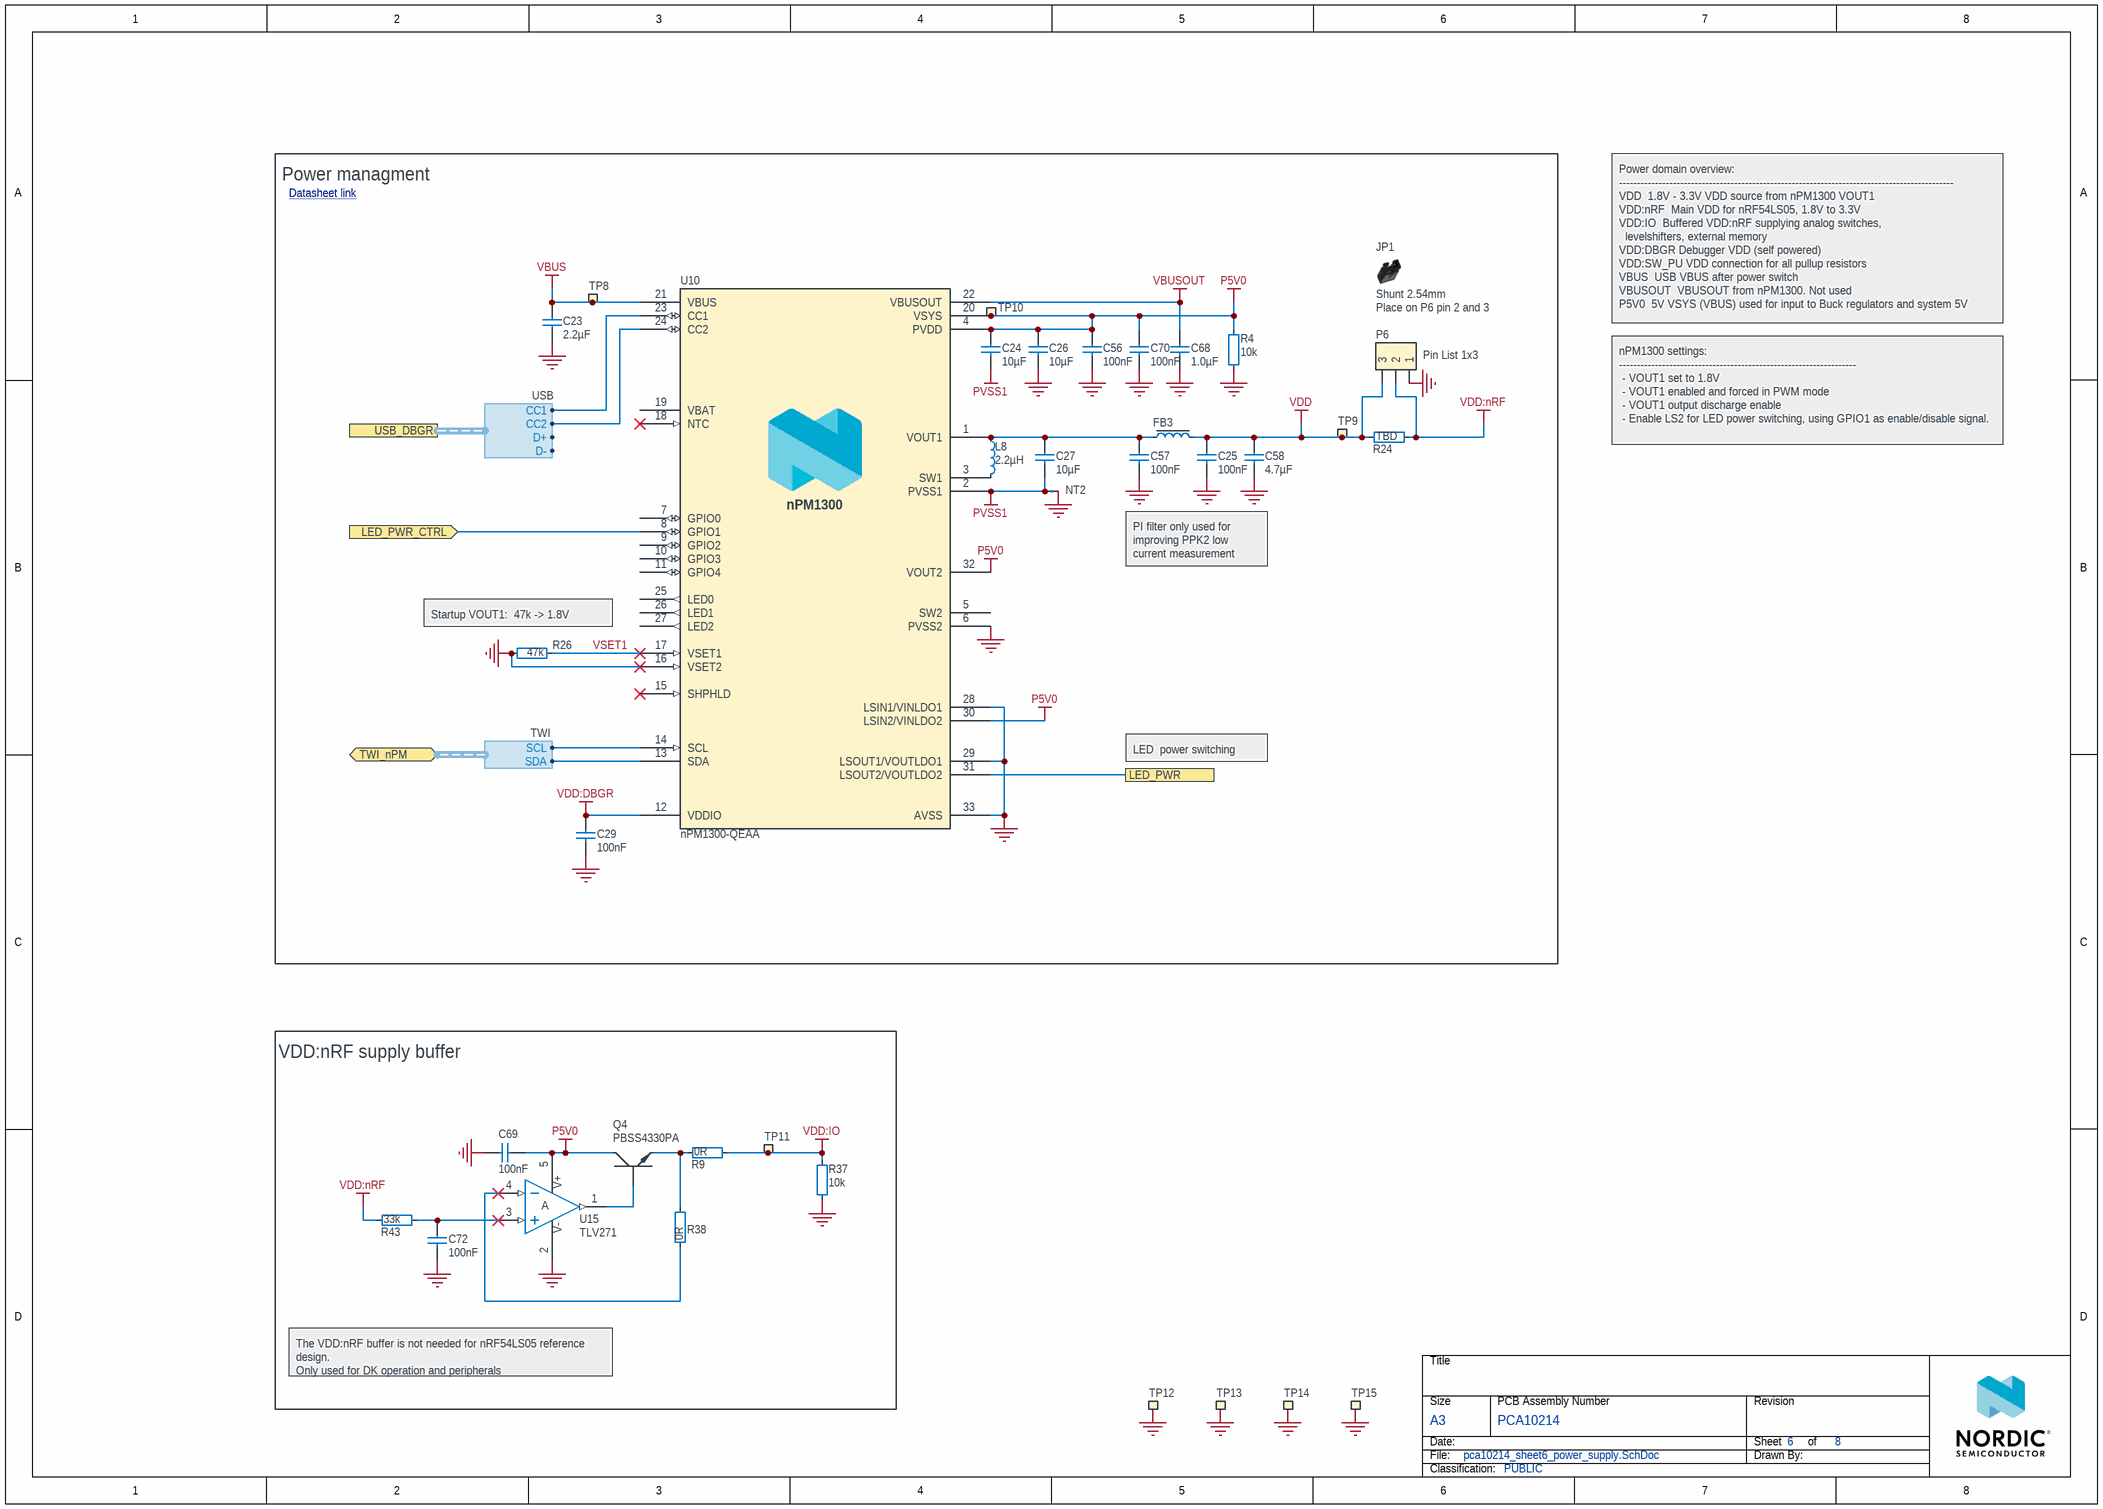
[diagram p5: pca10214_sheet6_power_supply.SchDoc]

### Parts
C23  2.2µF  [CAPC1005X04L]
C24  10µF  [CAPC1608X06L]
C25  100nF  [CAPC0603X03L_C]
C26  10µF  [CAPC1608X06L]
C27  10µF  [CAPC1608X06L]
C29  100nF  [CAPC0603X03L_C]
C56  100nF  [CAPC0603X03L_C]
C57  100nF  [CAPC0603X03L_C]
C58  4.7µF  [CAPC1608X06L]
C68  1.0µF  [CAPC1005X04L]
C69  100nF  [CAPC0603X03L_C]
C70  100nF  [CAPC0603X03L_C]
C72  100nF  [CAPC0603X03L_C]
FB3  120R/0.55A  [INDC1005X04L]  (value not drawn)
JP1  Shunt 2.54mm  Assembly: Place on P6 pin 2 and 3  [Shunt_2.54mm_Vertical]
L8  2.2µH  [INDC2016X10N]
NT2  Net tie  [2 PIN STARPOINT]  (value not drawn)  (net tie, no BOM)
P6  Pin List 1x3  [LIST_1x3_SMD]
Q4  PBSS4330PA  [DFN105P200X65-3N_v2]
R4  10k  [RESC0603X03L_C]
R9  0R  [RESC0603X03L_C]
R24  TBD  [RESC1005X04L]
R26  47k  [RESC0603X03L_C]
R37  10k  [RESC0603X03L_C]
R38  0R  [RESC0603X03L_C]
R43  33k  [RESC0603X03L_C]
TP8  Ø1.5mm,SMD  [TP_SMD_D1.5mm]  (value not drawn)  (no BOM)
TP9  Ø1.5mm,SMD  [TP_SMD_D1.5mm]  (value not drawn)  (no BOM)
TP10  Ø1.5mm,SMD  [TP_SMD_D1.5mm]  (value not drawn)  (no BOM)
TP11  Ø1.5mm,SMD  [TP_SMD_D1.5mm]  (value not drawn)  (no BOM)
TP12  Ø1.5mm,SMD  [TP_SMD_D1.5mm]  (value not drawn)  (no BOM)
TP13  Ø1.5mm,SMD  [TP_SMD_D1.5mm]  (value not drawn)  (no BOM)
TP14  Ø1.5mm,SMD  [TP_SMD_D1.5mm]  (value not drawn)  (no BOM)
TP15  Ø1.5mm,SMD  [TP_SMD_D1.5mm]  (value not drawn)  (no BOM)
U10  nPM1300-QEAA  [Nordic_QFN50P500X500X90-33N]
U15  TLV271  [SOT95P280X145-5N]

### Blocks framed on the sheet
Power managment: C23-C27 C29 C56-C58 C68 C70 FB3 JP1 L8 NT2 P6 R4 R24 R26 TP8-TP10 U10
VDD:nRF supply buffer: C69 C72 Q4 R9 R37 R38 R43 TP11 U15

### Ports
LED_PWR, LED_PWR_CTRL (in), TWI_nPM (bidir, harness TWI), USB_DBGR (harness USB)

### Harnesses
TWI: SDA, SCL
USB: D+, D-, CC1, CC2

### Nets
GND: C23.1 C25.1 C26.1 C29.2 C56.1 C57.1 C58.2 C68.1 C69.2 C70.1 C72.2 NT2.1 P6.1 R4.1 R26.2 R37.1 TP12.1 TP13.1 TP14.1 TP15.1 U10.6(PVSS2) U10.16(VSET2) U10.28(LSIN1/VINLDO1) U10.29(LSOUT1/VOUTLDO1) U10.33(AVSS) U15.2(VSS)
P5V0: C24.2 C26.2 C56.2 C69.1 C70.2 Q4.3(C) R4.2 TP10.1 U10.4(PVDD) U10.20(VSYS) U10.30(LSIN2/VINLDO2) U10.32(VOUT2) U15.5(VDD)
PVSS1: C24.1 C27.1 NT2.2 U10.2(PVSS1)
VBUS: C23.2 TP8.1 U10.21(VBUS)
VBUSOUT: C68.2 U10.22(VBUSOUT)
VDD: C25.2 C58.1 FB3.2 P6.3 R24.2 TP9.1
VDD:DBGR: C29.1 U10.12(VDDIO)
VDD:IO: R9.2 R37.2 TP11.1
VDD:nRF: P6.2 R24.1 R43.1
LED_PWR_CTRL: U10.8(GPIO1) ; port LED_PWR_CTRL
TWI0_SCL: U10.14(SCL) ; port TWI_nPM.SCL
TWI0_SDA: U10.13(SDA) ; port TWI_nPM.SDA
VSET1: R26.1 U10.17(VSET1)
NetC27_2: C27.2 C57.2 FB3.1 L8.1 U10.1(VOUT1)
NetC64_2: U10.31(LSOUT2/VOUTLDO2) ; port LED_PWR
NetC72_1: C72.1 R43.2 U15.3(IN+)
NetJ3_A5: U10.23(CC1) ; port USB_DBGR.CC1
NetJ3_B5: U10.24(CC2) ; port USB_DBGR.CC2
NetL8_2: L8.2 U10.3(SW1)
NetQ4_1: Q4.1(B) U15.1(OUT)
NetQ4_2: Q4.2(E) R9.1 R38.2
NetR38_1: R38.1 U15.4(IN-)

Not connected (* = marked no-connect by the designer): U10 5(SW2) 7(GPIO0) 9(GPIO2) 10(GPIO3) 11(GPIO4) 15(SHPHLD)* 18(NTC)* 19(VBAT) 25(LED0) 26(LED1) 27(LED2)

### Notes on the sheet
- Datasheet link <https://www.nordicsemi.com/Products/nPM1300>
- Power domain overview:
  ---------------------------------------------------------------------------------------------
  VDD		1.8V - 3.3V VDD source from nPM1300 VOUT1
  VDD:nRF		Main VDD for nRF54LS05, 1.8V to 3.3V
  VDD:IO		Buffered VDD:nRF supplying analog switches,
  levelshifters, external memory
  VDD:DBGR	Debugger VDD (self powered)
  VDD:SW_PU	VDD connection for all pullup resistors
  VBUS		USB VBUS after power switch
  VBUSOUT		VBUSOUT from nPM1300. Not used
  P5V0		5V VSYS (VBUS) used for input to Buck regulators and system 5V
- nPM1300 settings:
  ------------------------------------------------------------------
  - VOUT1 set to 1.8V
  - VOUT1 enabled and forced in PWM mode
  - VOUT1 output discharge enable
  - Enable LS2 for LED power switching, using GPIO1 as enable/disable signal.
- PI filter only used for improving PPK2 low current measurement accuracy
- (near R26) Startup VOUT1:  47k -> 1.8V
- LED  power switching
- The VDD:nRF buffer is not needed for nRF54LS05 reference design.
  Only used for DK operation and peripherals

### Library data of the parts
C23 = C0402-2µ2-10V: Capacitor, X5R, ±10%; Manufacturer: N.A.; Part number NEMS: 100200376; Component Status: Active; Pad Count: 2; Note: 10V
C24 C26 C27 = C0603-10µ-10V-X7T-GRM188D71A106MA73: Capacitor, X7T, ±20%, 10V; Manufacturer: Murata; Part number IPS: 00000004696; Part number NEMS: 100200414; Component Status: Active; Pad Count: 2; Note: 10VDC; Artikkelnr Noca: N.A.
C25 C56 C57 C70 = C0201-100n: as C64 on sheet pca10214_sheet5_misc
C29 C69 C72 = C0201-100n: as C18 on sheet pca10214_sheet3_debugger
C58 = C0603-4µ7-10V-X7S: as C42 on sheet pca10214_sheet3_debugger
C68 = C0402-1µ0-6.3V-X5R-10%: as C31 on sheet pca10214_sheet3_debugger
FB3 = FB0402-120R@100M-500mA: Ferrite Bead, 120 Ohm @ 100MHz, 500mA, 250 mOhm Max; Manufacturer: Murata; Manufacturer Part Number: BLM15AG121SN1D; Part number IPS: 00000009954; Part number Norautron: 265230631; Part number NEMS: 100300099; Note: Chip EMIFIL Inductor Type Chip Ferrite Bead; Artikkelnr Noca: 33029317; Pad Count: 2; Component Status: Active
JP1 = SHUNT JUMPER 2.54mm Black Vertical: Shunt Jumper 2.54mm Black, open top; Manufacturer: WCON; Manufacturer Part Number: 3710-6001OS0B05; Part number NEMS: 100500728; Pad Count: 2; Note: N.A.; Component Status: Active; System: Connector
L8 = L0806-2µ2-2500mA-73mOhm-CIGT201610EH2R2MNE: Inductor, Irms=2.5A, Isat=2.9A, ±20%, DCR=73mΩ; Manufacturer: Samsung Electro-Mechanics America; Part number Norautron: 26521789; Part number NEMS: 100300400; Component Status: Active; Pad Count: 2; Note: Unshielded Thin Film Inductor; Artikkelnr Noca: N.A.
NT2 = 2 pin starpoint: Starpoint; Manufacturer: N.A.; Part number NEMS: 100500603; Pad Count: 2; Component Status: Active; System: Connector
P6 = Pin List 1x3 SMD: Pin List 1x3, 2.54mm (100mil), SMD; Manufacturer: WCON; Manufacturer Part Number: 1125-1103S0M116CR04; Part number Norautron: 26470016; Part number NEMS: 100500306; Note: N.A.; Pad Count: 3; Component Status: Active; System: Connector
Q4 = PBSS4330PA,115: 30V, 3A, 2.1W, G=270, NPN Transistor; Manufacturer: Nexperia; Part number NEMS: 101300184; Component Status: Active; Pad Count: 3; Note: N.A.
R4 R37 = R0201-10k: as R41 on sheet pca10214_sheet3_debugger
R9 R38 = R0201-0R: Resistor, ±5%, 0.05W; Manufacturer: N.A.; Part number IPS: 00000003245; Part number NEMS: 100100001; Component Status: Active; Pad Count: 2; Note: Chip Res 5%
R24 = R0402-TBD: Chip Res 0402; Manufacturer: N.A.; Part number NEMS: 100100282; Component Status: Active; Pad Count: 2
R26 = R0201-47k: Resistor, ±1%, 0.05W; Manufacturer: N.A.; Part number IPS: 00000001423; Part number NEMS: 100100076; Component Status: Active; Pad Count: 2; Note: Chip Res 1%
R43 = R0201-33k: Resistor, ±1%, 0.05W; Manufacturer: N.A.; Part number IPS: 00000001708; Part number NEMS: 100100073; Component Status: Active; Pad Count: 2; Note: Chip Res 1%
TP8-TP15 = TP_SMD_Ø1.5MM: as TP1 on sheet pca10214_sheet2_nRF54LS05
U10 = nPM1300-QEAA: Li-Ion/Li-Polymer USB-C battery charger with high efficiency buck regulators, LDOs or load switches, LED drivers, TWI and VBUSOUT; Manufacturer: Nordic Semiconductor; Part number NEMS: 102000291; Component Status: Active; Pad Count: 33; Note: N.A.
U15 = TLV271CW5-7: Dual rail to rail CMOS Amplifier; Manufacturer: Diodes Incorporated; Part number NEMS: 101900398; Component Status: Active; Pad Count: 5; Note: N.A.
